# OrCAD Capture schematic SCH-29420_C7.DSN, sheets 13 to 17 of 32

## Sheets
13 P11_MX8QM_GND: size A2
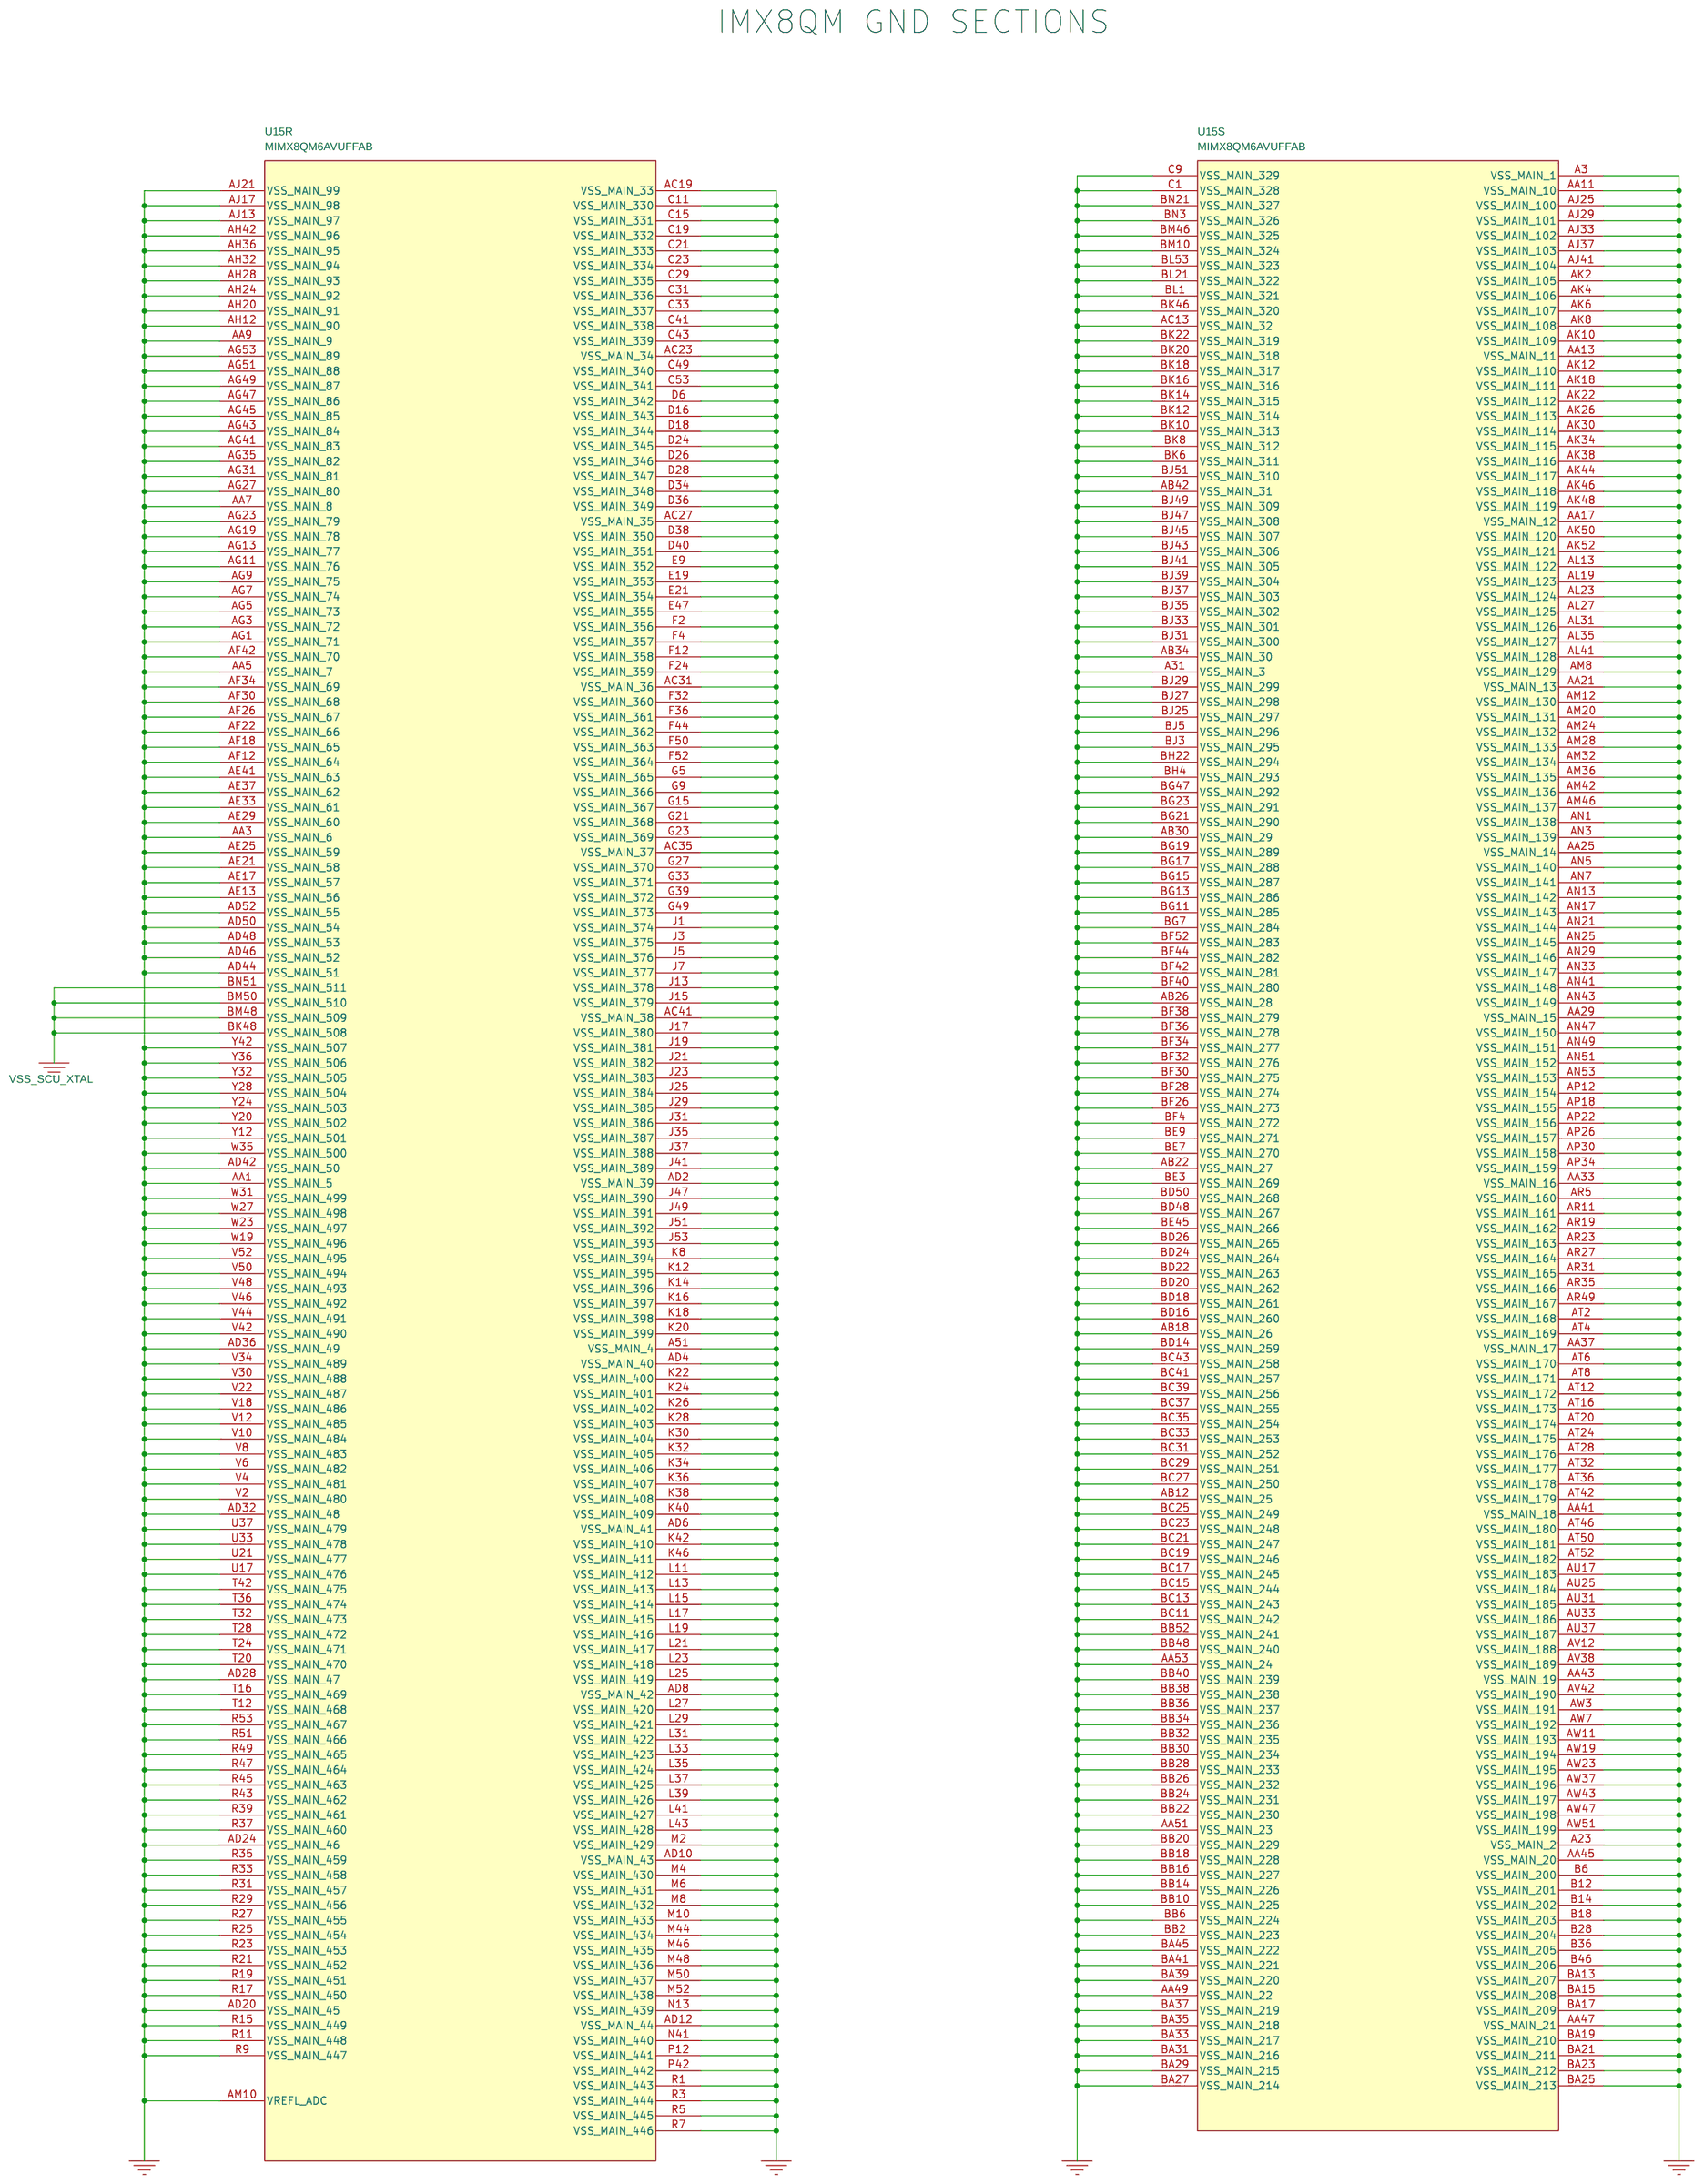
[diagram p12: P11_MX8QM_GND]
14 P12_MX8QM_SECTIONS_1: size A1
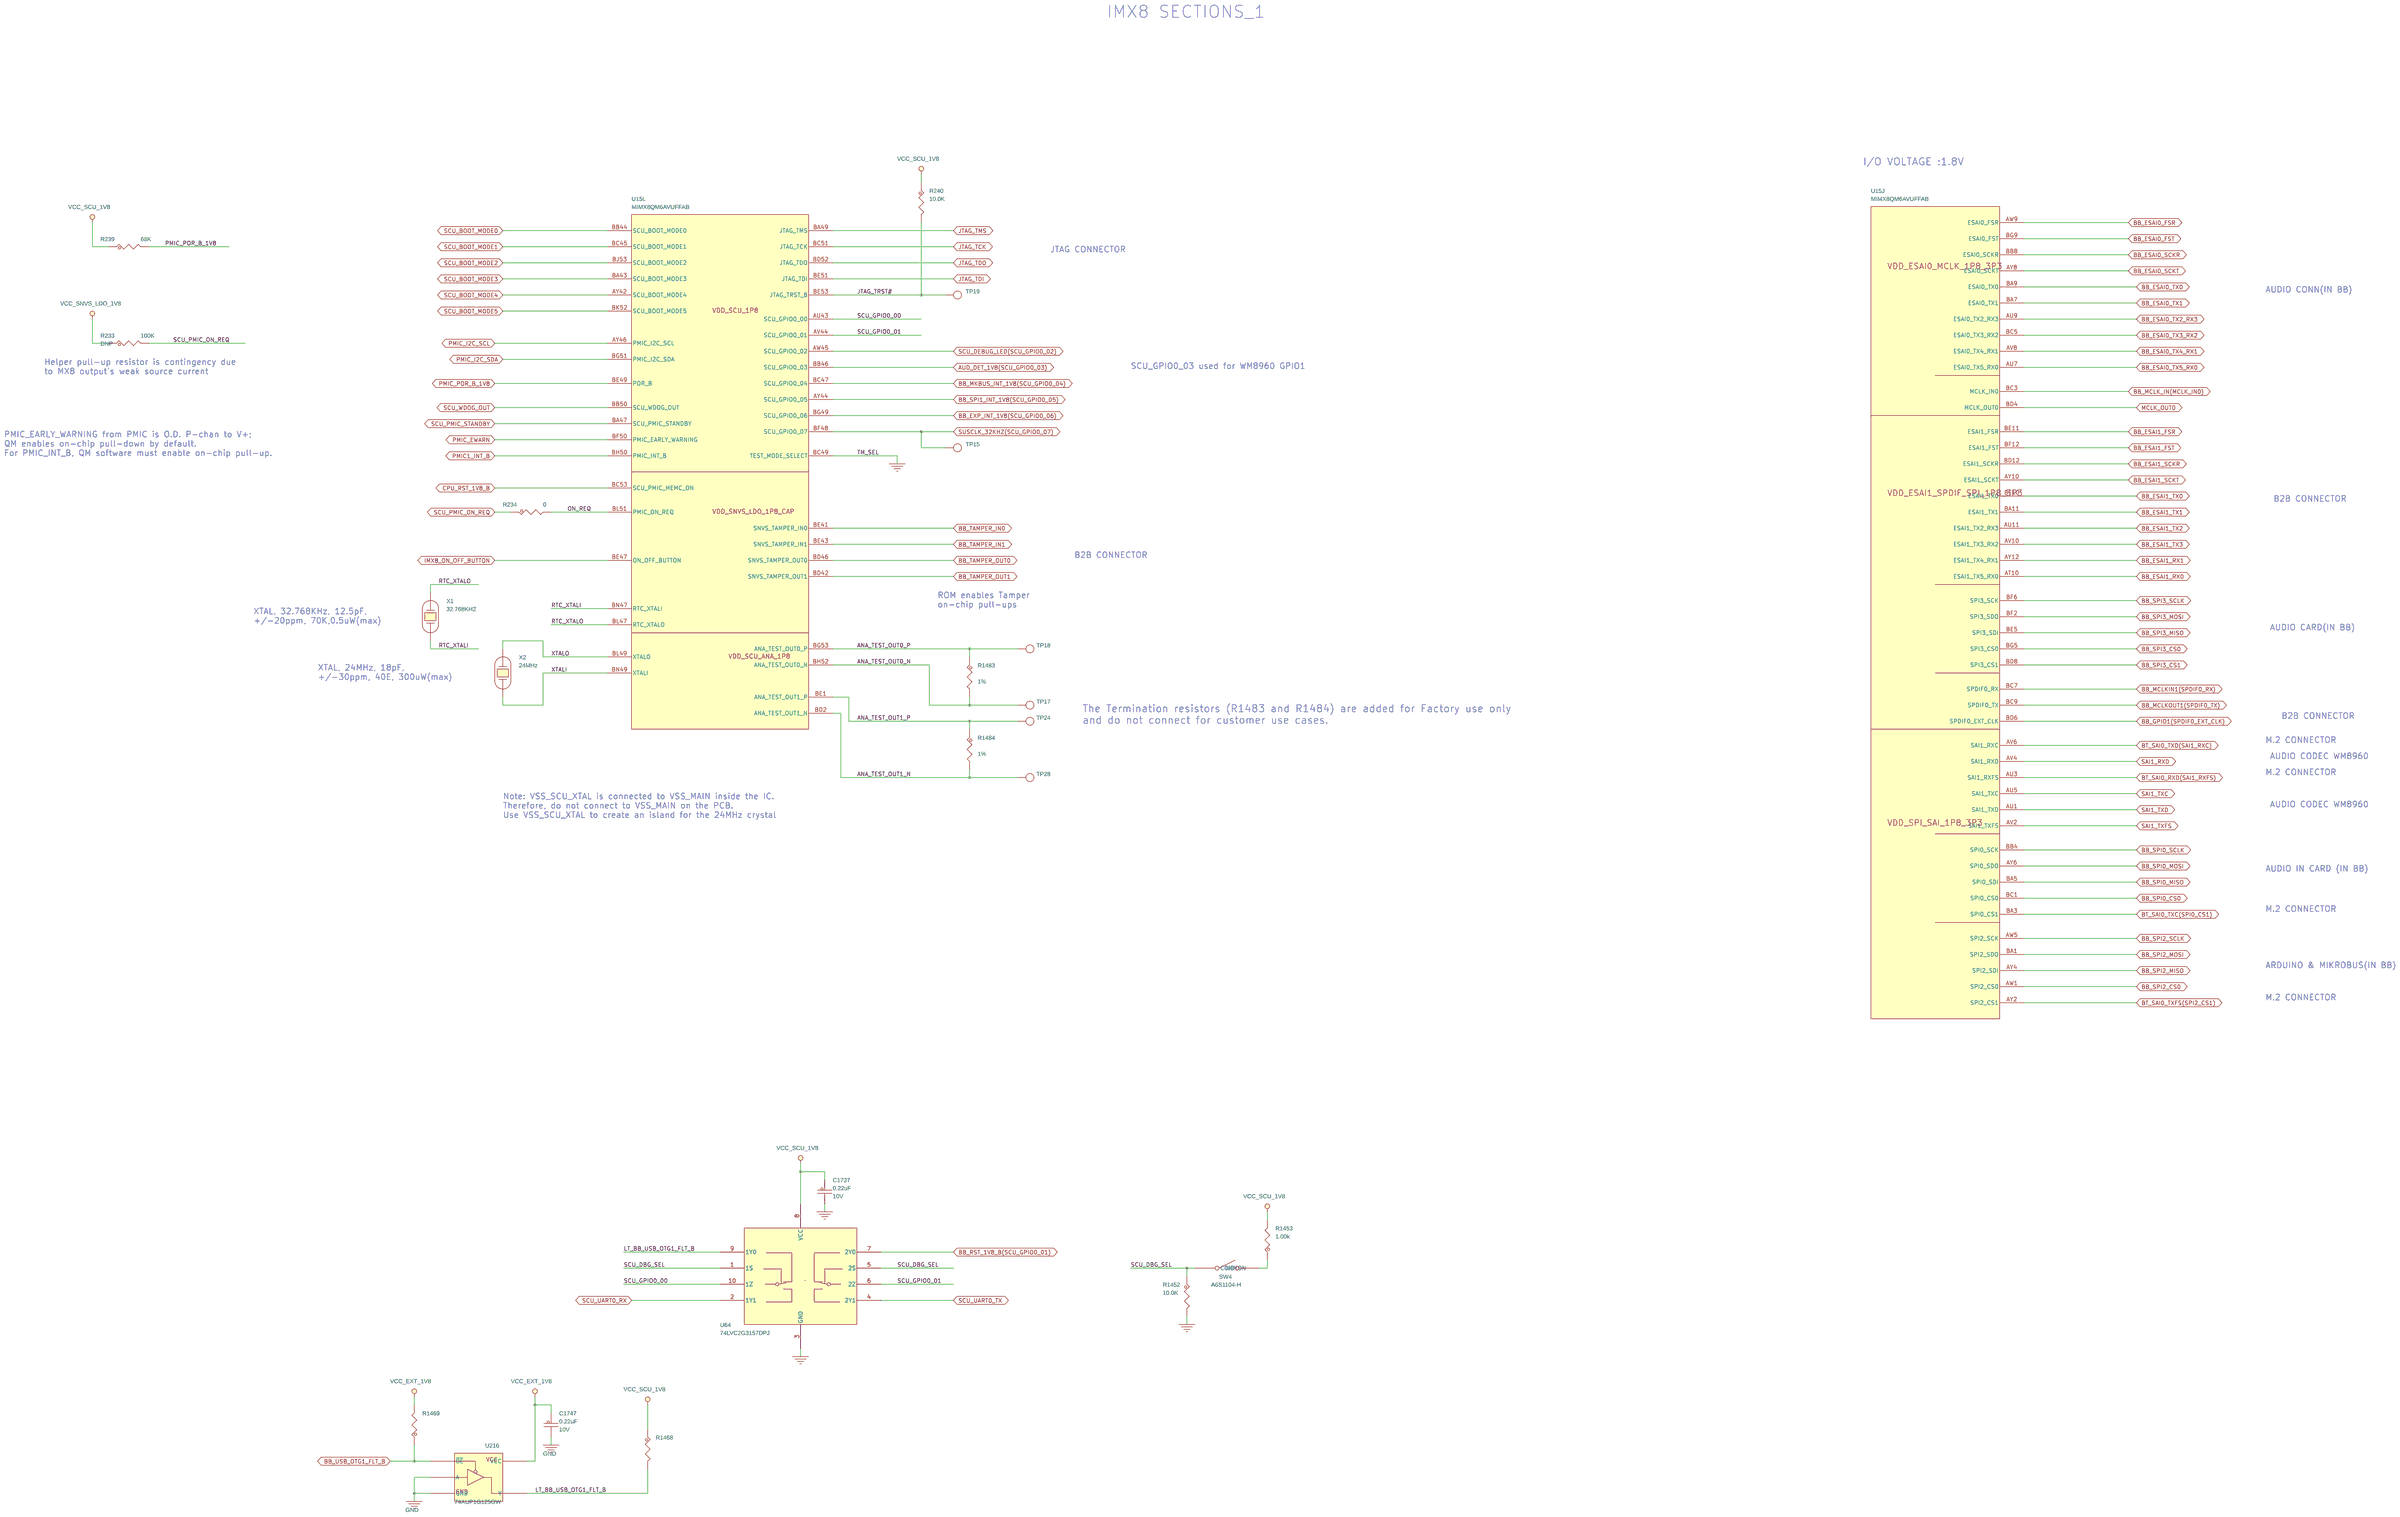
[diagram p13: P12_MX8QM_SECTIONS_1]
15 P13_MX8QM_SECTIONS_2: size A2
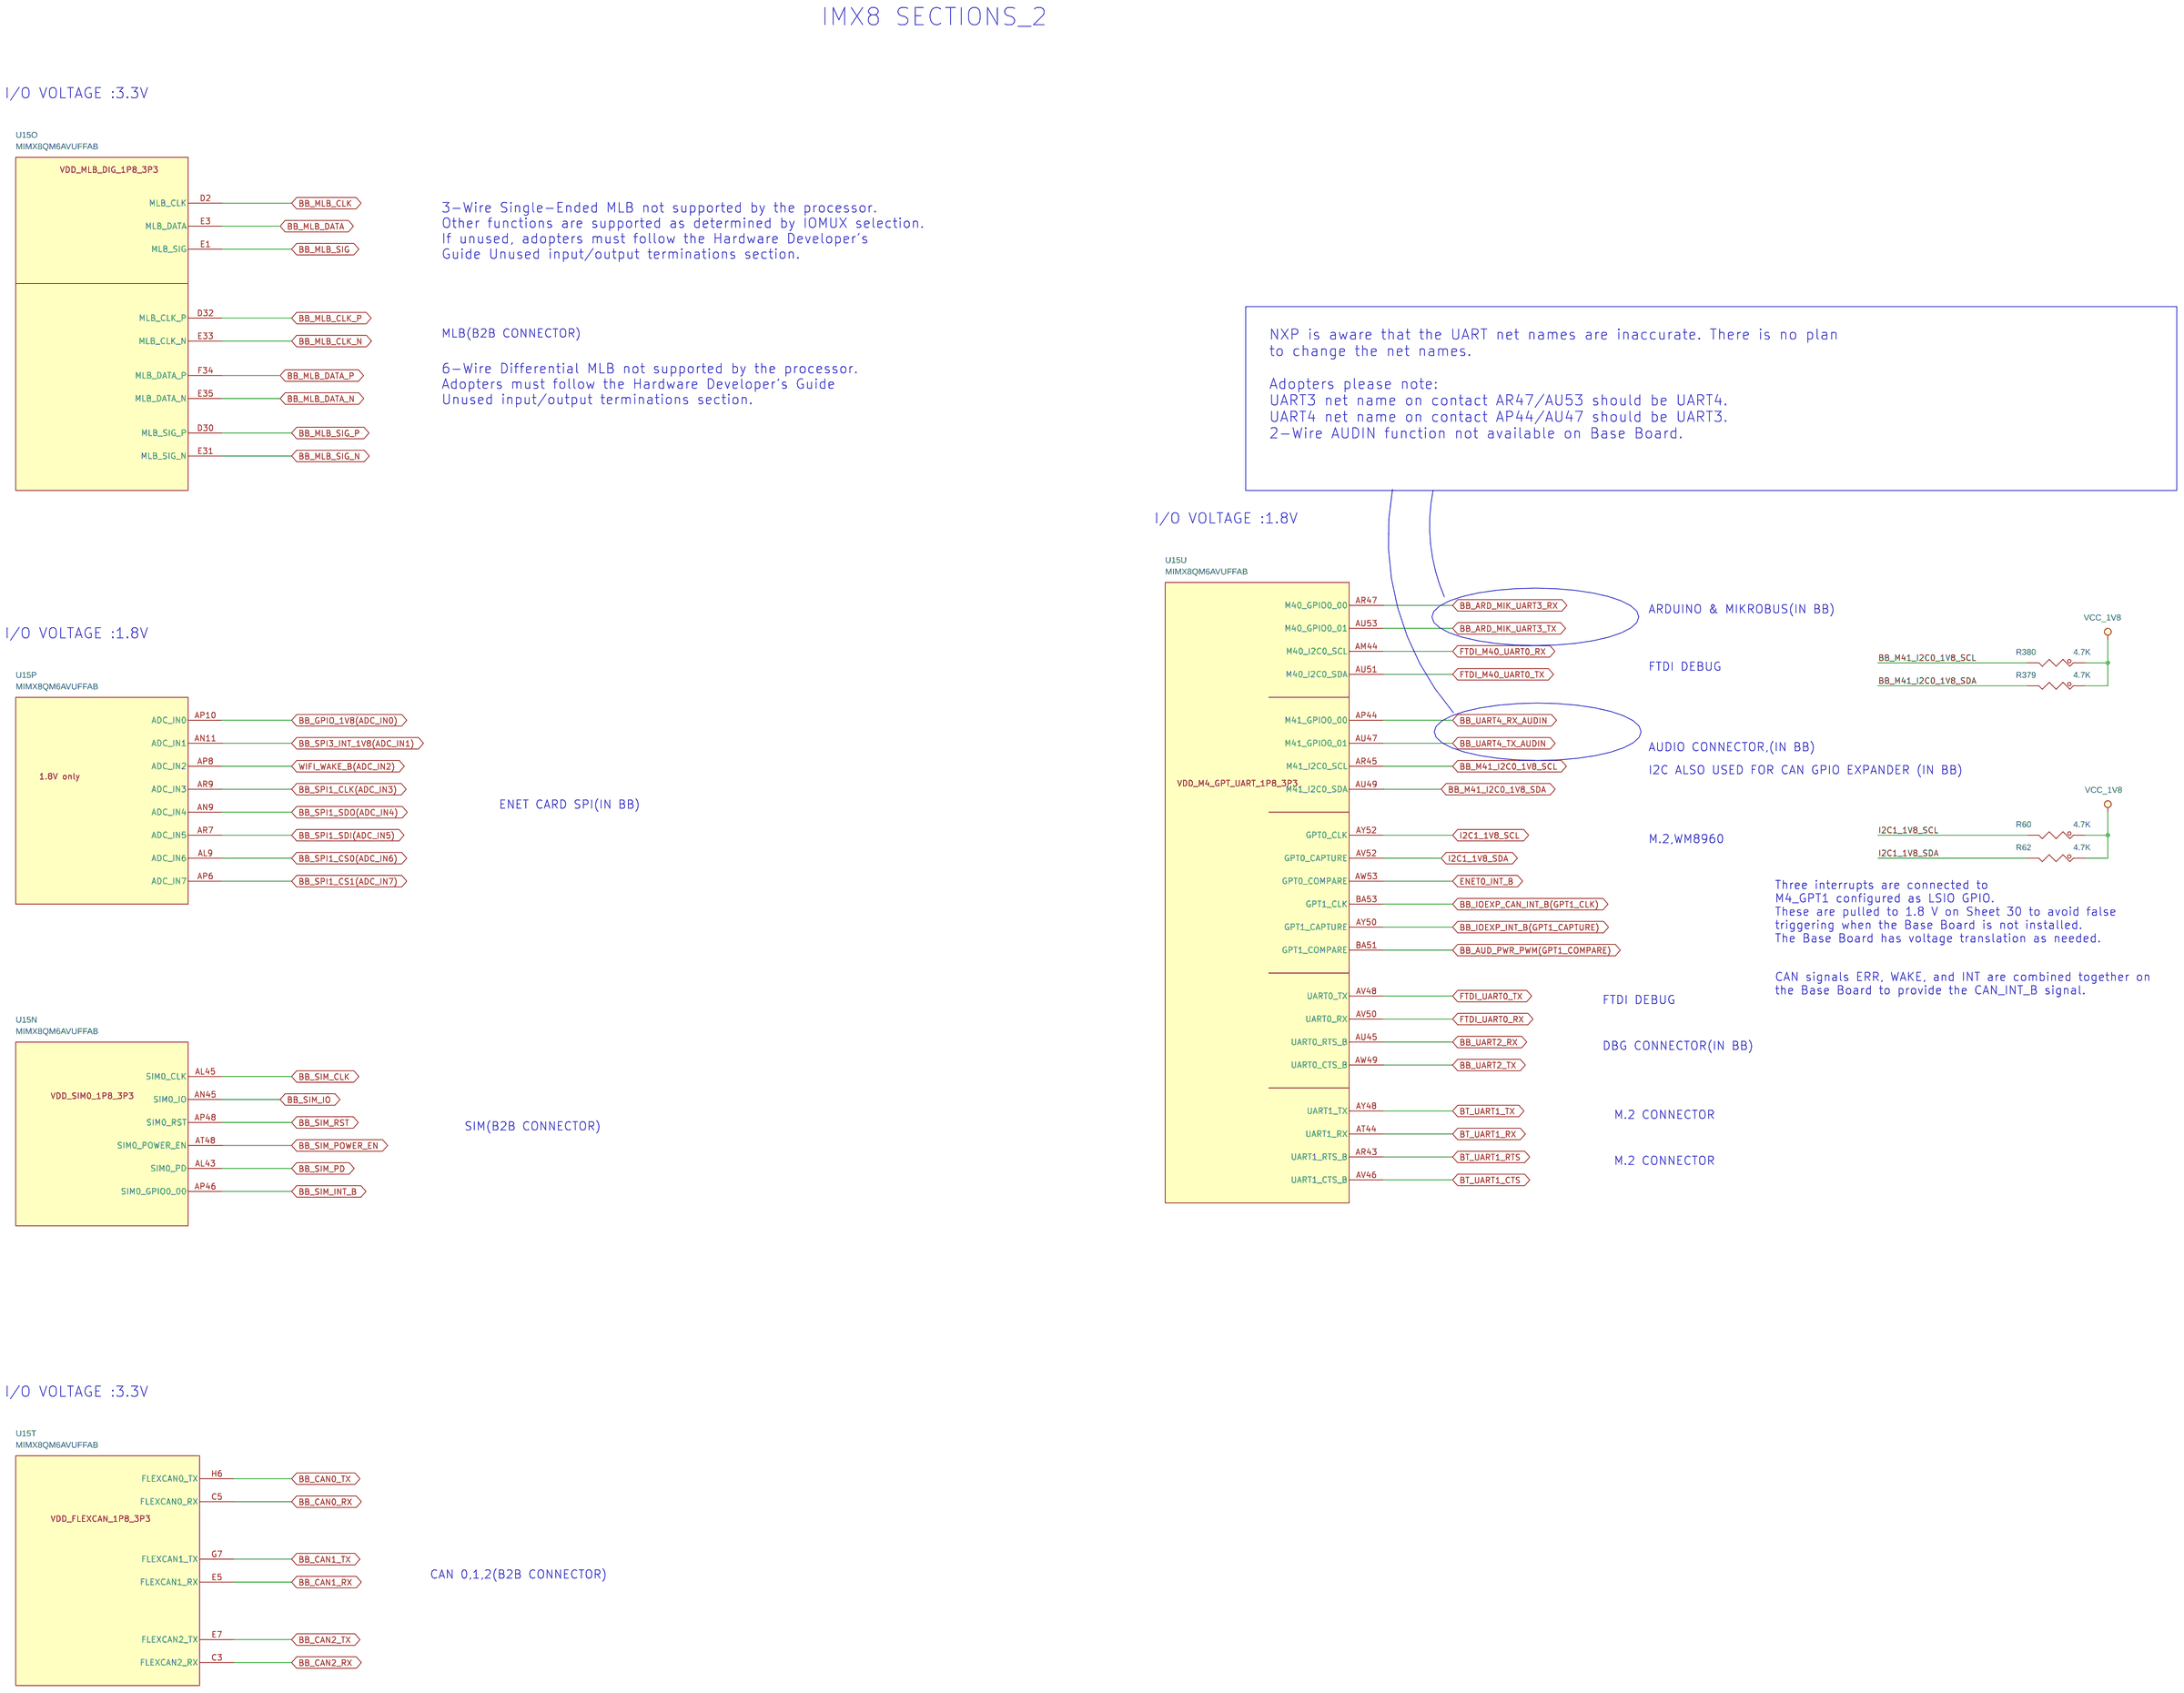
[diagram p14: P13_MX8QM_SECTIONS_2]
16 P14_LPDDR4_DRAM_1: size A2
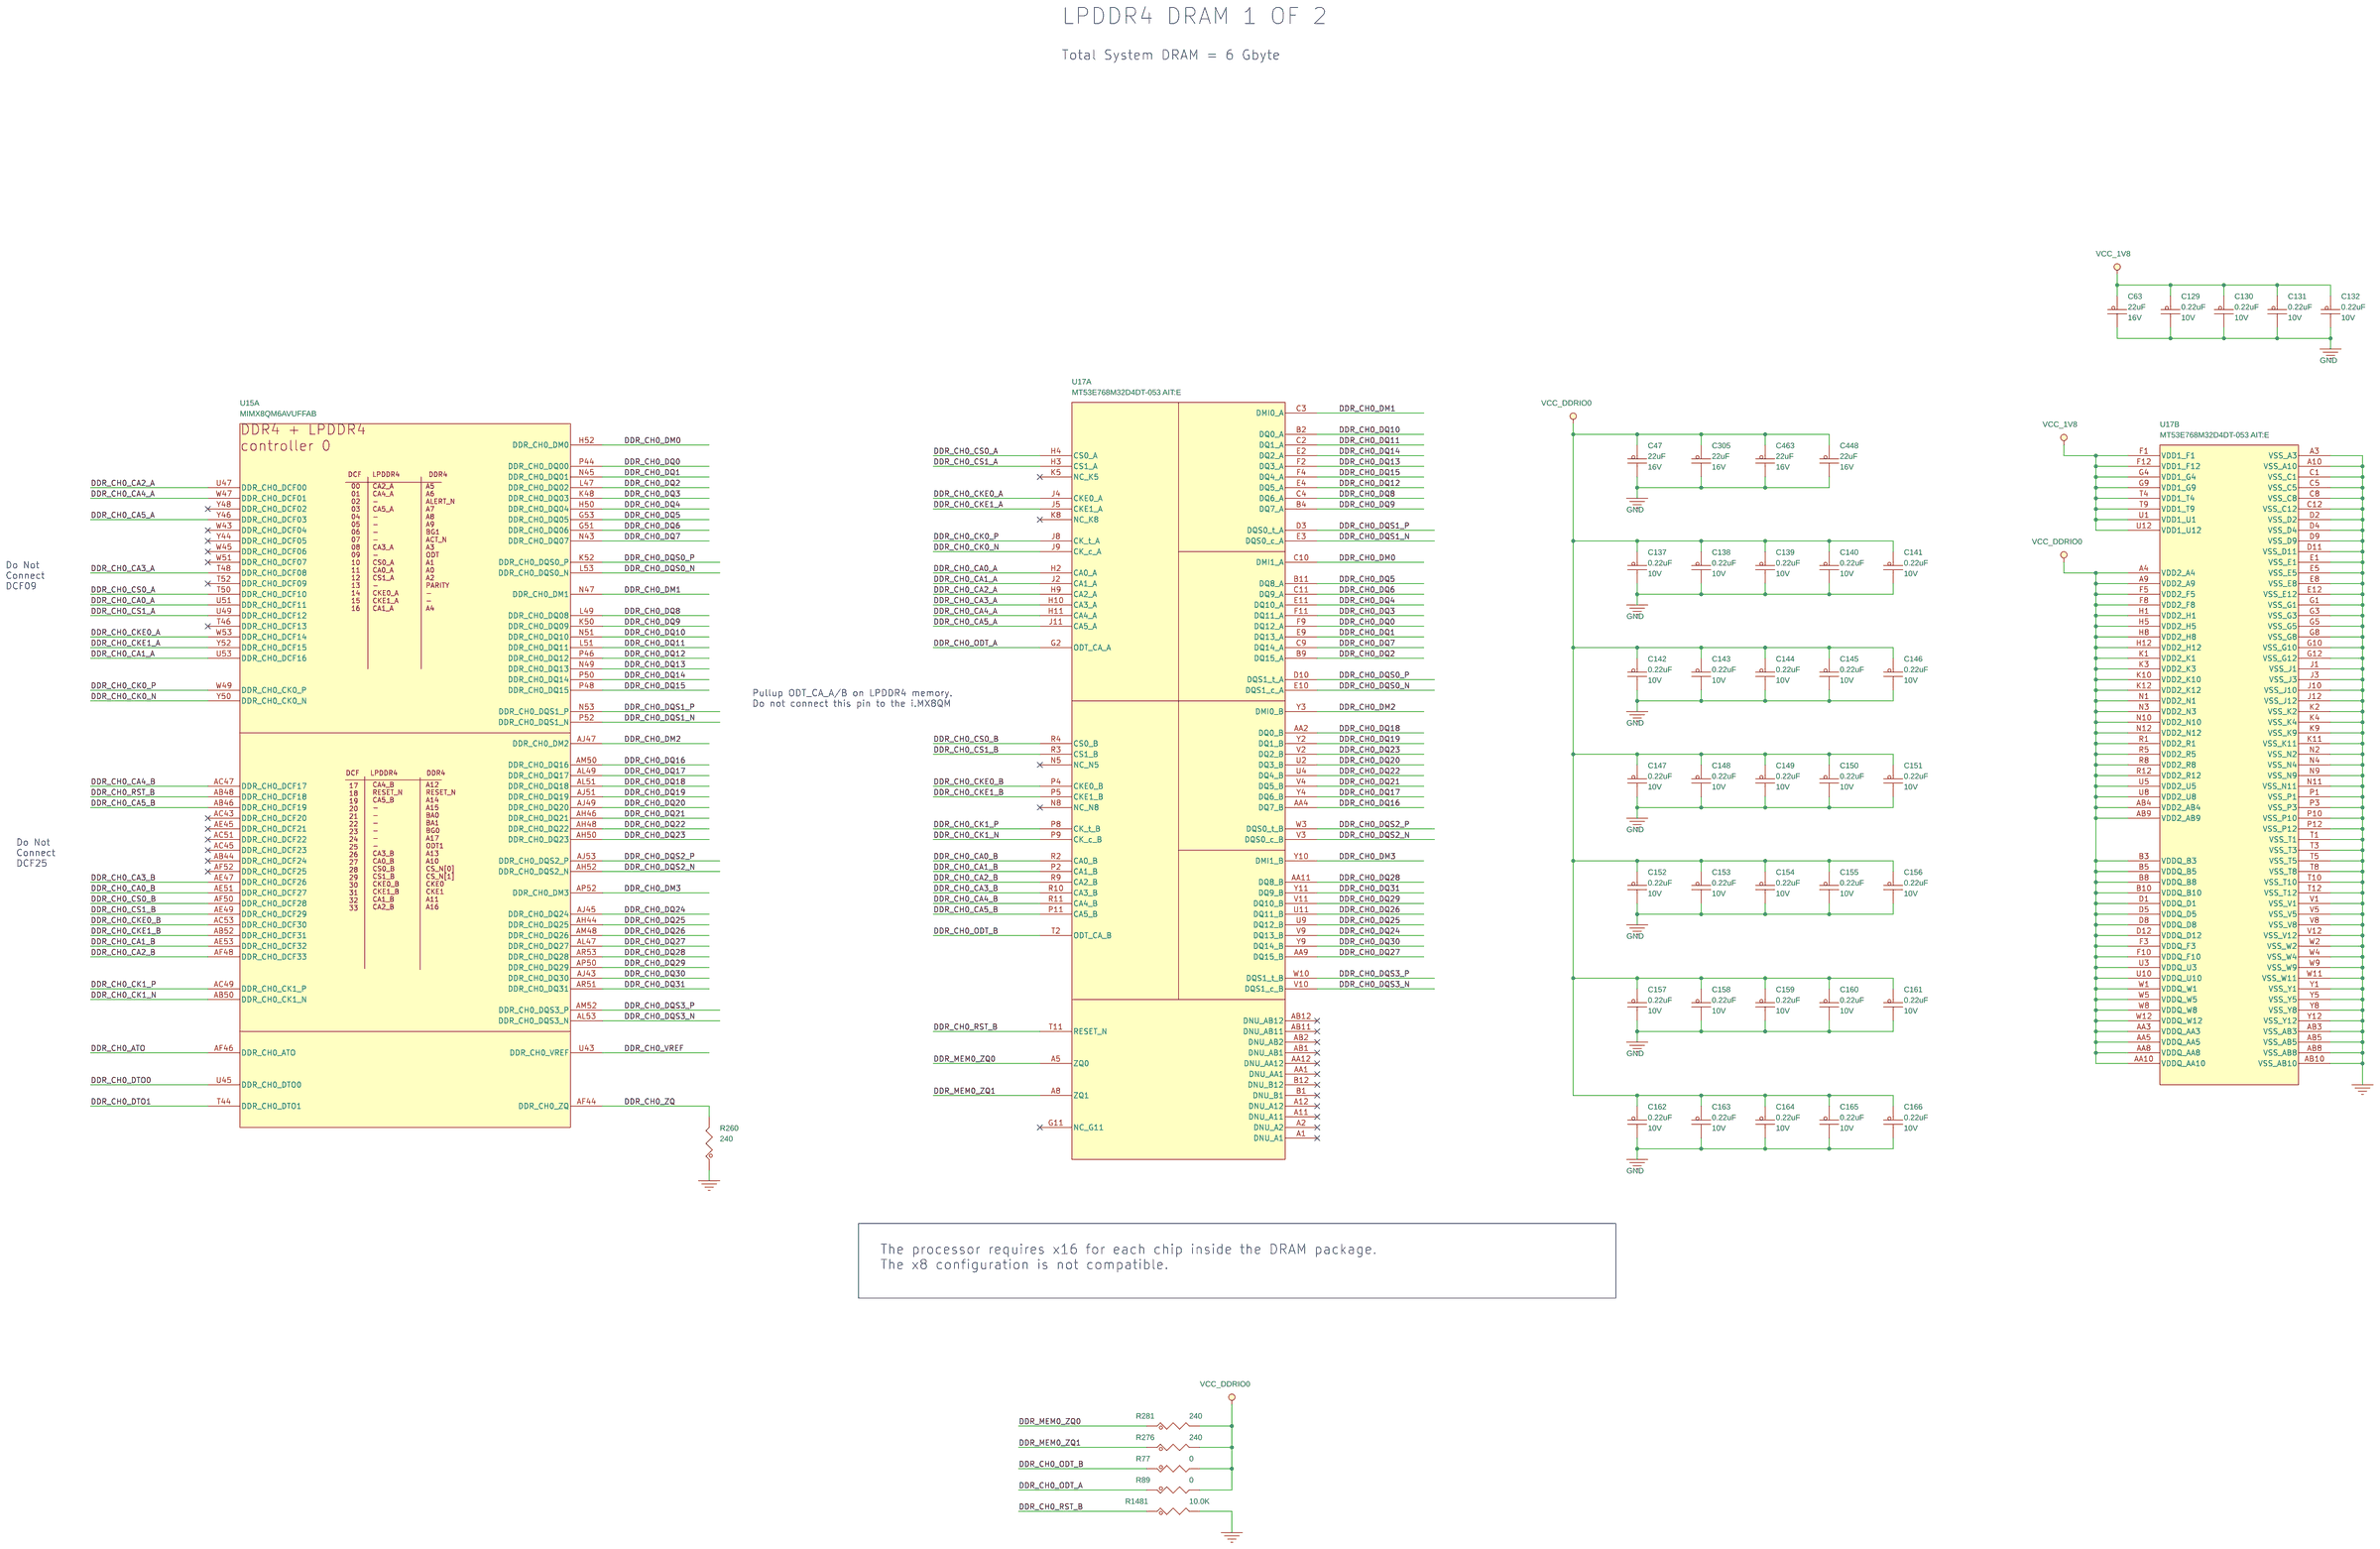
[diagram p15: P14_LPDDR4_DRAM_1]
17 P15_LPDDR4_DRAM_2: size A2
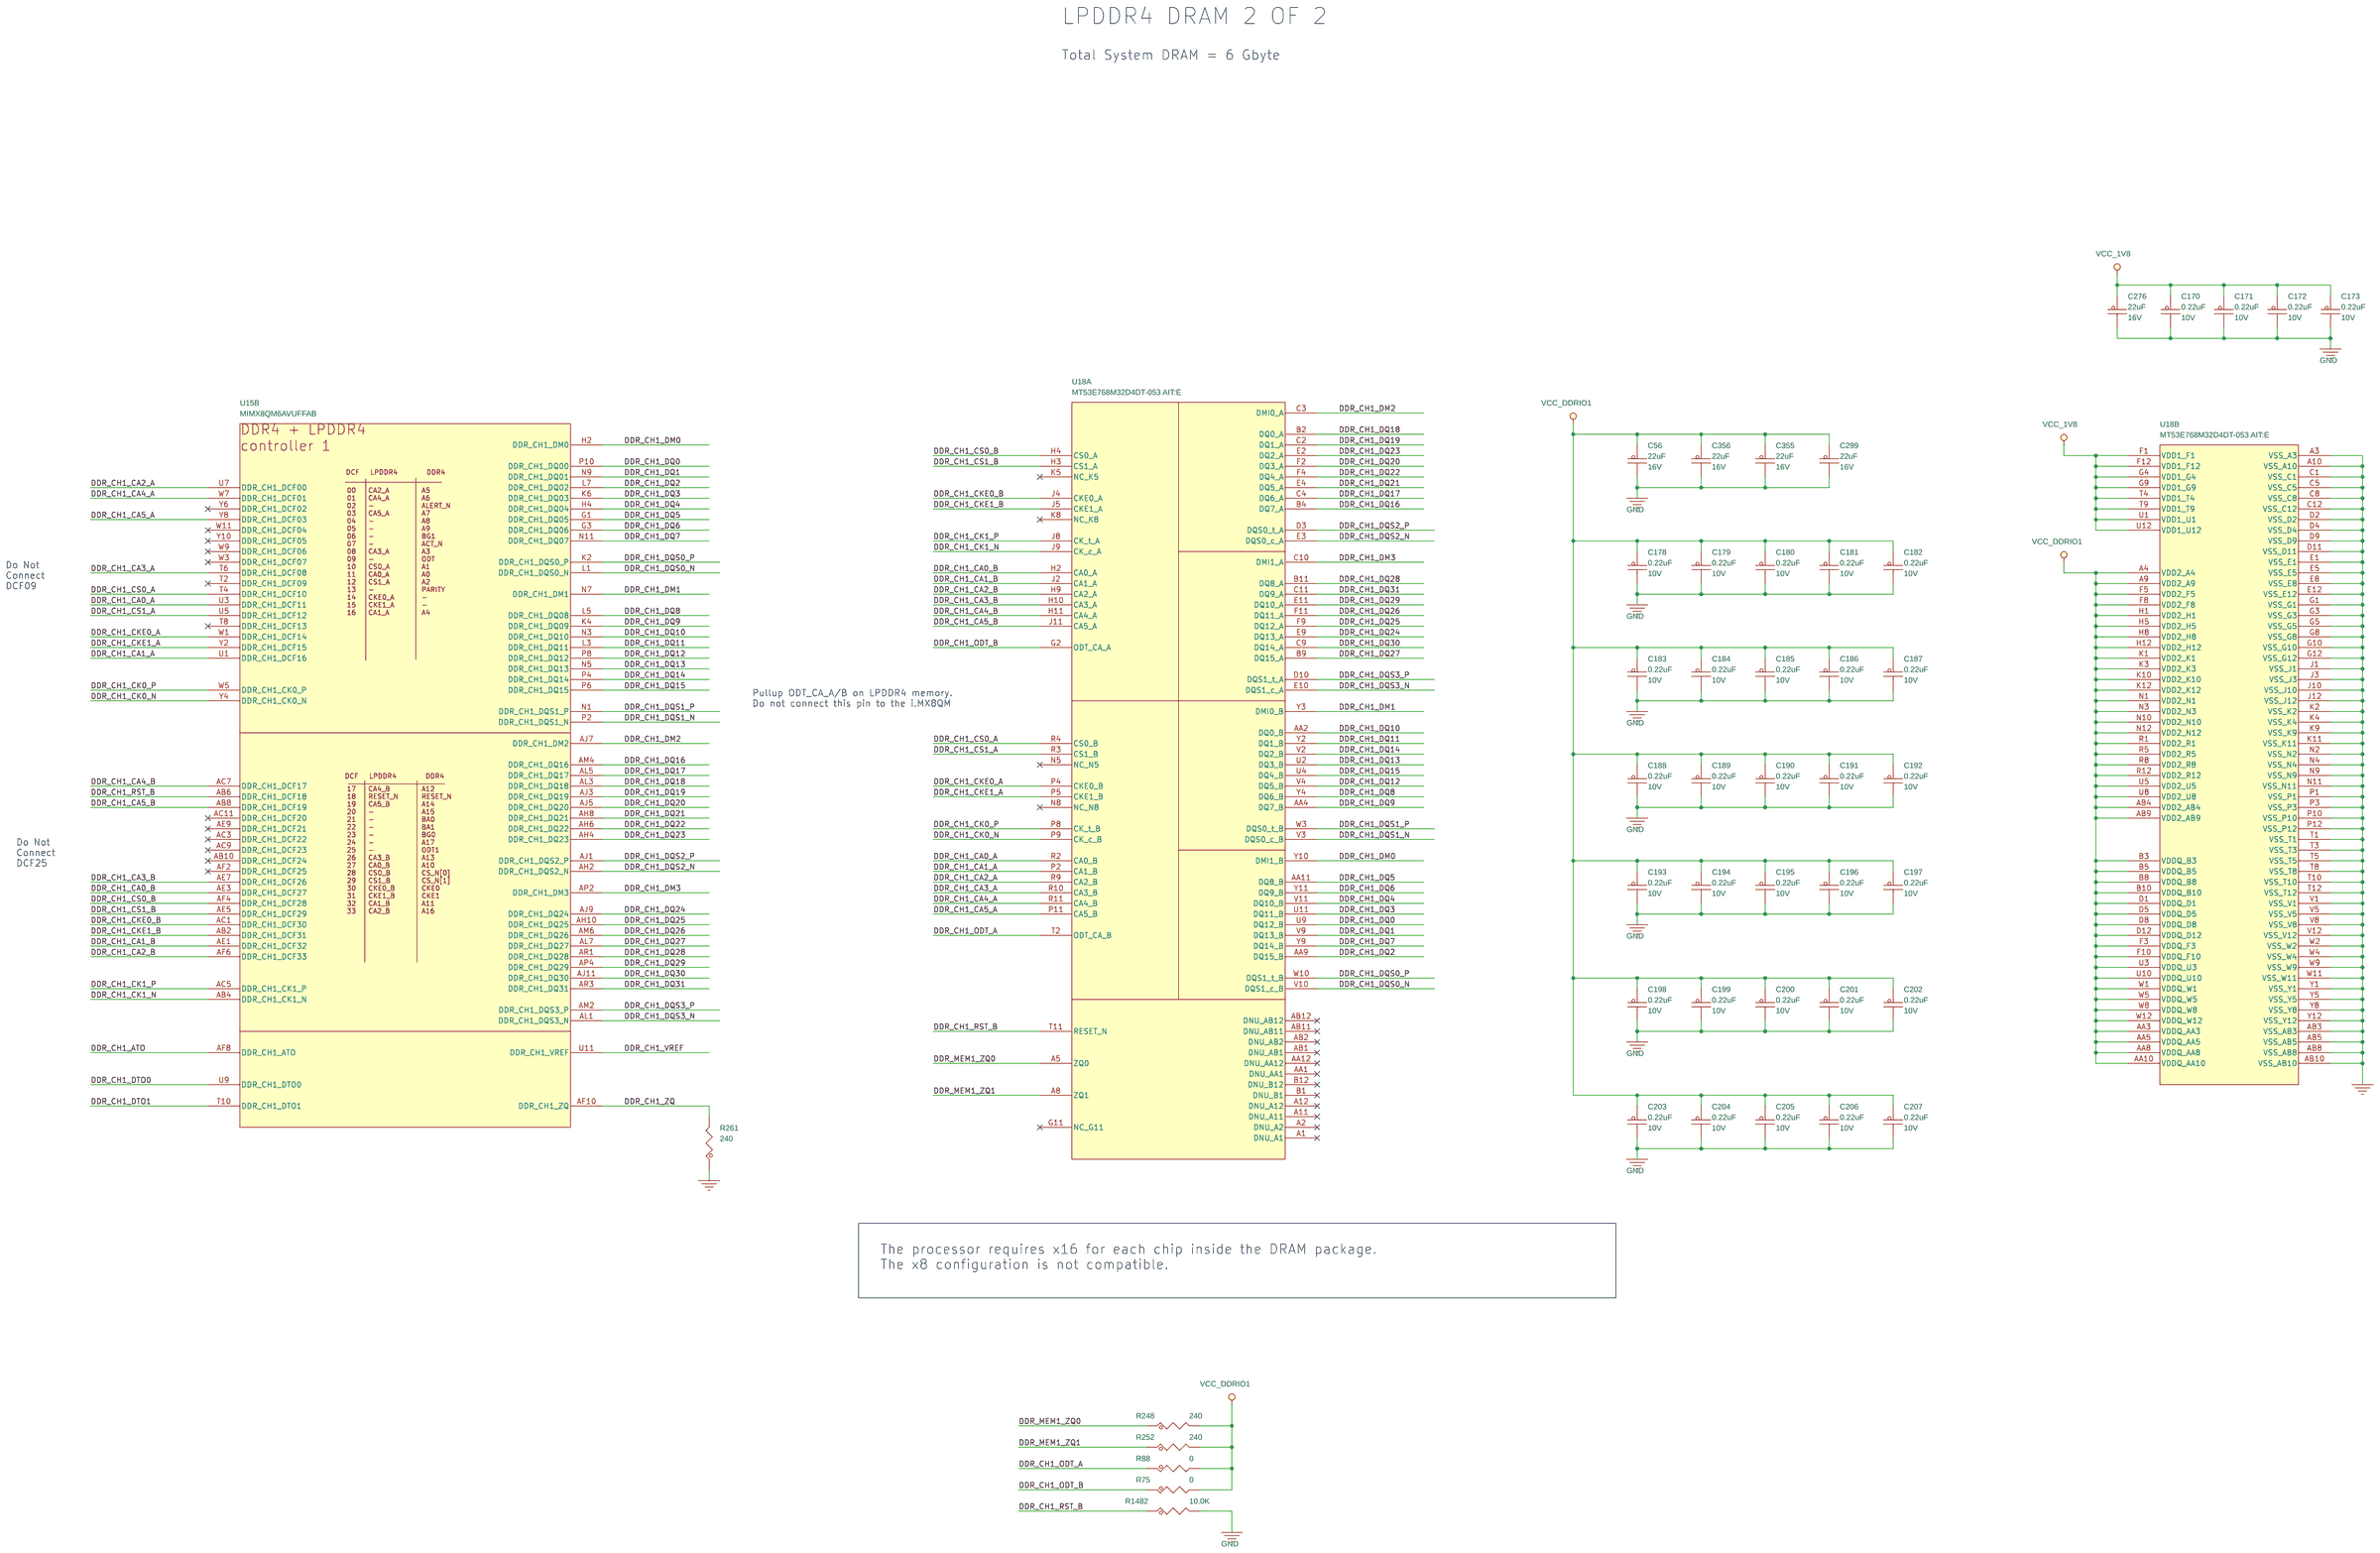
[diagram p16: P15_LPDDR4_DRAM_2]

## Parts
sheet P12_MX8QM_SECTIONS_1
C1737  0.22uF  [CC0402_25]
C1747  0.22uF  [0402_CC]
R233  100K  [RC0402_25]
R234  0  [RC0402_25]
R239  68K  [RC0402_25]
R240  10.0K  [RC0402_25]
R1452  10.0K  [RC0402_25]
R1453  1.00k  [RC0402_25]
R1468  10K  [RC0402_25]
R1469  68K  [RC0402_25]
R1483  100  [RC0402_25]
R1484  100  [RC0402_25]
SW4  A6S1104-H  [sw2_6p4x3p68_sm]
TP15  TPAD_050  [TPAD_050]
TP17  TPAD_020  [tpad_020]
TP18  TPAD_020  [tpad_020]
TP19  TPAD_050  [TPAD_050]
TP24  TPAD_020  [tpad_020]
TP28  TPAD_020  [tpad_020]
U64  74LVC2G3157DPJ  [TSSOP10_0P5_3X3MM]
U216  74AUP1G125GW  [SC70-5]
X1  32.768KHZ  [XTAL2-3P2X1P5-SM]
X2  24MHz  [xtal2_4_5p2x3p4]
sheet P13_MX8QM_SECTIONS_2
R60  4.7K  [RC0402_25]
R62  4.7K  [RC0402_25]
R379  4.7K  [RC0402_25]
R380  4.7K  [RC0402_25]
sheet P14_LPDDR4_DRAM_1
C47  22uF  [CC1210]
C63  22uF  [CC1210]
C129  0.22uF  [CC0402_25]
C130  0.22uF  [CC0402_25]
C131  0.22uF  [CC0402_25]
C132  0.22uF  [CC0402_25]
C137  0.22uF  [CC0402_25]
C138  0.22uF  [CC0402_25]
C139  0.22uF  [CC0402_25]
C140  0.22uF  [CC0402_25]
C141  0.22uF  [CC0402_25]
C142  0.22uF  [CC0402_25]
C143  0.22uF  [CC0402_25]
C144  0.22uF  [CC0402_25]
C145  0.22uF  [CC0402_25]
C146  0.22uF  [CC0402_25]
C147  0.22uF  [CC0402_25]
C148  0.22uF  [CC0402_25]
C149  0.22uF  [CC0402_25]
C150  0.22uF  [CC0402_25]
C151  0.22uF  [CC0402_25]
C152  0.22uF  [CC0402_25]
C153  0.22uF  [CC0402_25]
C154  0.22uF  [CC0402_25]
C155  0.22uF  [CC0402_25]
C156  0.22uF  [CC0402_25]
C157  0.22uF  [CC0402_25]
C158  0.22uF  [CC0402_25]
C159  0.22uF  [CC0402_25]
C160  0.22uF  [CC0402_25]
C161  0.22uF  [CC0402_25]
C162  0.22uF  [CC0402_25]
C163  0.22uF  [CC0402_25]
C164  0.22uF  [CC0402_25]
C165  0.22uF  [CC0402_25]
C166  0.22uF  [CC0402_25]
C305  22uF  [CC1210]
C448  22uF  [CC1210]
C463  22uF  [CC1210]
R77  0  [RC0402_25]
R89  0  [RC0402_25]
R260  240  [RC0402_25]
R276  240  [RC0402_25]
R281  240  [RC0402_25]
R1481  10.0K  [RC0402_25]
U17  MT53E768M32D4DT-053 AIT:E  [bga200_0p65x0p8_10p1x14p6]  (sections A,B)
sheet P15_LPDDR4_DRAM_2
C56  22uF  [CC1210]
C170  0.22uF  [CC0402_25]
C171  0.22uF  [CC0402_25]
C172  0.22uF  [CC0402_25]
C173  0.22uF  [CC0402_25]
C178  0.22uF  [CC0402_25]
C179  0.22uF  [CC0402_25]
C180  0.22uF  [CC0402_25]
C181  0.22uF  [CC0402_25]
C182  0.22uF  [CC0402_25]
C183  0.22uF  [CC0402_25]
C184  0.22uF  [CC0402_25]
C185  0.22uF  [CC0402_25]
C186  0.22uF  [CC0402_25]
C187  0.22uF  [CC0402_25]
C188  0.22uF  [CC0402_25]
C189  0.22uF  [CC0402_25]
C190  0.22uF  [CC0402_25]
C191  0.22uF  [CC0402_25]
C192  0.22uF  [CC0402_25]
C193  0.22uF  [CC0402_25]
C194  0.22uF  [CC0402_25]
C195  0.22uF  [CC0402_25]
C196  0.22uF  [CC0402_25]
C197  0.22uF  [CC0402_25]
C198  0.22uF  [CC0402_25]
C199  0.22uF  [CC0402_25]
C200  0.22uF  [CC0402_25]
C201  0.22uF  [CC0402_25]
C202  0.22uF  [CC0402_25]
C203  0.22uF  [CC0402_25]
C204  0.22uF  [CC0402_25]
C205  0.22uF  [CC0402_25]
C206  0.22uF  [CC0402_25]
C207  0.22uF  [CC0402_25]
C276  22uF  [CC1210]
C299  22uF  [CC1210]
C355  22uF  [CC1210]
C356  22uF  [CC1210]
R75  0  [RC0402_25]
R88  0  [RC0402_25]
R248  240  [RC0402_25]
R252  240  [RC0402_25]
R261  240  [RC0402_25]
R1482  10.0K  [RC0402_25]
U18  MT53E768M32D4DT-053 AIT:E  [bga200_0p65x0p8_10p1x14p6]  (sections A,B)
sheet P20_USB3.x_TYPE_C
U15  MIMX8QM6AVUFFAB  [imx8_bga_1313]  (sections A,B,C,D,E,F,G,H,I,J,K,L,M,N,O,P,Q,R,S,T,U)

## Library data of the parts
C129-C132 C137-C166 C170-C173 C178-C207 C1737 C1747 = CAP_NP: CAP CER 0.22uF 10V 10% X7R AEC-Q200 0402; AGILE_PN: 150-79031; CAD_APPROVED: Yes; EN: 102-1-01816; FPLIST: CC0402_25,CC0402_HD,0402_CC; HEIGHT: 0.55MM; MFG_NAME01: TDK; MFG_PN01: CGA2B1X7R1A224K050BC; ROHS: Yes; TOL: 10%; Tolerance: 10%; VOLTAGE: 10V
R233 = RES: RES MF 100K 1/16W 5% 0402; AGILE_PN: 470-75597; ASSY_OPT: DNP; CAD_APPROVED: Yes; EN: 101-1-02817; FPLIST: RC0402_25,RC0402_HD,0402_CC; HEIGHT: 0.40 MM; MFG_NAME01: VENKEL COMPANY; MFG_PN01: CR0402-16W-104JT; ROHS: Yes; TOL: 5%; Tolerance: 5%
R75 R77 R88 R89 R234 = RES: RES MF ZERO OHM 1/16W -- AEC-Q200 0402; AGILE_PN: 470-80742; CAD_APPROVED: Yes; EN: 101-1-00001; FPLIST: RC0402_25,RC0402_HD,0402_CC; HEIGHT: 0.45 MM; MFG_NAME01: VISHAY INTERTECHNOLOGY; MFG_PN01: CRCW04020000Z0ED; ROHS: Yes
R239 = RES: RES MF 68K 1/16W 5% 0402; AGILE_PN: 470-30330; CAD_APPROVED: Yes; EN: 101-1-02813; FPLIST: RC0402_25,RC0402_HD,0402_CC; HEIGHT: 0.4MM; MFG_NAME01: TYCO ELECTRONICS; MFG_PN01: CRG0402J68K; ROHS: Yes; TOL: 5%; Tolerance: 5%
R240 R1452 R1481 R1482 = RES: RES MF 10.0K 1/16W 1% 0402; AGILE_PN: 470-80574; CAD_APPROVED: Yes; EN: 101-1-00389; FPLIST: RC0402_25,RC0402_HD,0402_CC; HEIGHT: 0.4MM; MFG_NAME01: WALSIN TECHNOLOGY CORP.; MFG_PN01: WR04X1002FTL; ROHS: Yes; TOL: 1%; Tolerance: 1%
R1453 = RES: RES MF 1.00k Ohm 1/16W 1% AEC-Q200 0402; AGILE_PN: 470-80511; CAD_APPROVED: Yes; EN: 101-1-00293; FPLIST: RC0402_25,RC0402_HD,0402_CC; HEIGHT: 0.4 MM; MFG_NAME01: KOA SPEER; MFG_PN01: RK73H1ETTP1001F; ROHS: Yes; TOL: 1%; Tolerance: 1%
R1468 = RES: RES MF 10K 1/16W 5% 0402; AGILE_PN: 470-75557; CAD_APPROVED: Yes; EN: 101-1-02793; FPLIST: RC0402_25,RC0402_HD,0402_CC; HEIGHT: 0.4 MM; MFG_NAME01: VISHAY INTERTECHNOLOGY; MFG_PN01: CRCW040210K0JNED; ROHS: Yes; TOL: 5%; Tolerance: 5%
R1469 = RES: RES MF 68K  1/16W 1% AEC-Q200 0402; AGILE_PN: 470-31042; CAD_APPROVED: Yes; EN: 101-1-03542; FPLIST: RC0402_25,RC0402_HD,0402_CC; HEIGHT: 0.40 MM; MFG_NAME01: VISHAY INTERTECHNOLOGY; MFG_PN01: CRCW040268K0FKED; PRIORITY_PN: 006-00730; ROHS: Yes; ROOM: JTAG; SIGNAL_MODEL: DEFAULT_RESISTOR_68000OHM_2_1; TOL: 1%; Tolerance: 1%
R1483 R1484 = RES: RES MF 100 OHM 1/16W 1% 0402; AGILE_PN: 470-30454; CAD_APPROVED: Yes; EN: 101-1-00197; FPLIST: RC0402_25,RC0402_HD,0402_CC; HEIGHT: 0.4 MM; MFG_NAME01: THYE MING TECH CO LTD; MFG_PN01: CR-02FL6--100R; ROHS: Yes; SIGNAL_MODEL: DEFAULT_RESISTOR_100OHM_2_1; TOL: 1%; Tolerance: 1%
SW4 = SW2P: SW SPST DIP SLD 25mA 24V SMD; AGILE_PN: 510-78107; CAD_APPROVED: Yes; EN: 205-1-00234; HEIGHT: 4.5MM; MFG_NAME01: OMRON; MFG_PN01: A6S-1104-H; ROHS: Yes
TP15 TP19 = TESTLOOP: TEST POINT PAD 50MIL DIA SMT, NO PART TO ORDER; AGILE_PN: 211-76644; CAD_APPROVED: Yes; HEIGHT: 0.1MM; MFG_NAME01: NOTACOMPONENT; MFG_PN01: NOTACOMPONENT; ROHS: Yes
TP17 TP18 TP24 TP28 = TESTLOOP: TEST POINT PAD 0.5MM DIA SMT, NO PART TO ORDER; AGILE_PN: 211-77484; CAD_APPROVED: Yes; HEIGHT: 0.1MM; ROHS: Yes
U64 = 74LVC2G3157DPJ: IC LIN SW DUAL SPDT 1.65-5.5V TSSOP10; AGILE_PN: 315-81080; CAD_APPROVED: Yes; EN: 301-0-01547; HEIGHT: 1.1 MM; MFG_NAME01: NEXPERIA; MFG_PN01: 74LVC2G3157DP,118; ROHS: Yes
U216 = 1G125: IC BUFFER/LINE DRIVER 3STATE 0.8-3.6V SC70-5; AGILE_PN: 315-80956; CAD_APPROVED: Yes; EN: 301-0-01520; HEIGHT: 1.1MM; MFG_NAME01: NEXPERIA; MFG_PN01: 74AUP1G125GW,125; ROHS: Yes
X1 = XTAL: XTAL 32.768KHZ 12.5PF 20PPM 3.2X1.5MM SMT; AGILE_PN: 230-77653; CAD_APPROVED: Yes; EN: 108-1-00009; HEIGHT: 0.9MM; MFG_NAME01: Abracon Corporation; MFG_PN01: ABS07-32.768KHZ-T; ROHS: Yes
X2 = XTAL: XTAL 24MHz 18PF 5x3.2mm SMT; AGILE_PN: 230-78202; CAD_APPROVED: Yes; EN: 108-1-00039; HEIGHT: 1.35MM; MFG_NAME01: CTS; MFG_PN01: 445I23D24M00000; ROHS: Yes; Temp_Range: -40C to +85C
R60 R62 R379 R380 = RES: RES MF 4.7K 1/16W 5% 0402; AGILE_PN: 470-75626; CAD_APPROVED: Yes; EN: 101-1-02785; FPLIST: RC0402_25,RC0402_HD,0402_CC,RC0402_X2; HEIGHT: 0.41mm; MFG_NAME01: NIC COMPONENTS CORP; MFG_PN01: NRCL04J472TRF; ROHS: Yes; TOL: 5%; Tolerance: 5%
C47 C56 C63 C276 C299 C305 C355 C356 C448 C463 = CAP_NP: CAP CER 22uF 16V 20% X7R AEC-Q200 HF 1210; AGILE_PN: 150-79354; CAD_APPROVED: Yes; EN: 102-1-02278; FPLIST: CC1210,1210_CC; HEIGHT: 2.7MM; MFG_NAME01: Taiyo Yuden; MFG_PN01: EMK325B7226MMHT; ROHS: Yes; TOL: 20%; Tolerance: 20%; VOLTAGE: 16V
R248 R252 R260 R261 R276 R281 = RES: RES MF 240 OHM 1/16W 1% 0402; AGILE_PN: 470-30776; CAD_APPROVED: Yes; EN: 101-1-03473; FPLIST: RC0402_25,RC0402_HD,0402_CC; HEIGHT: 0.40 MM; MFG_NAME01: WALSIN TECHNOLOGY CORP.; MFG_PN01: WR04X2400FTL; ROHS: Yes; TOL: 1%; Tolerance: 1%
U17 U18 = MT53B768M32D4NQ_200P: IC MEM MOBILE LPDDR4 SDRAM 768 Meg x 32 1.1V VFBGA200; AGILE_PN: 334-77856; CAD_APPROVED: Yes; HEIGHT: 0.95MM; MFG_NAME01: MICRON; ROHS: Yes; Temp Range: -40C to +95C; VOLTAGE: 1.1V
U15 = PIMX8QM6AVUFFAB_BGA1313: IC CPU QUADMAX 2xA72 1.6GHz 4xA53 1.2GHZ M4 264MHZ FCPBGA1313; AGILE_PN: 330-77094; CAD_APPROVED: Yes; HEIGHT: 2.52MM; MFG_NAME01: NXP SEMICONDUCTORS; ROHS: Yes; Temp Range: -40°C to 125°C

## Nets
GND: C47.2 C56.2 C63.2 C129.2 C130.2 C131.2 C132.2 C137.2 C138.2 C139.2 C140.2 C141.2 C142.2 C143.2 C144.2 C145.2 C146.2 C147.2 C148.2 C149.2 C150.2 C151.2 C152.2 C153.2 C154.2 C155.2 C156.2 C157.2 C158.2 C159.2 C160.2 C161.2 C162.2 C163.2 C164.2 C165.2 C166.2 C170.2 C171.2 C172.2 C173.2 C178.2 C179.2 C180.2 C181.2 C182.2 C183.2 C184.2 C185.2 C186.2 C187.2 C188.2 C189.2 C190.2 C191.2 C192.2 C193.2 C194.2 C195.2 C196.2 C197.2 C198.2 C199.2 C200.2 C201.2 C202.2 C203.2 C204.2 C205.2 C206.2 C207.2 C276.2 C299.2 C305.2 C355.2 C356.2 C448.2 C463.2 C1737.2 C1747.2 R260.1 R261.1 R1452.2 R1481.2 R1482.2 U15.A3(VSS_MAIN_1) U15.A23(VSS_MAIN_2) U15.A31(VSS_MAIN_3) U15.A51(VSS_MAIN_4) U15.AA1(VSS_MAIN_5) U15.AA3(VSS_MAIN_6) U15.AA5(VSS_MAIN_7) U15.AA7(VSS_MAIN_8) U15.AA9(VSS_MAIN_9) U15.AA11(VSS_MAIN_10) U15.AA13(VSS_MAIN_11) U15.AA17(VSS_MAIN_12) U15.AA21(VSS_MAIN_13) U15.AA25(VSS_MAIN_14) U15.AA29(VSS_MAIN_15) U15.AA33(VSS_MAIN_16) U15.AA37(VSS_MAIN_17) U15.AA41(VSS_MAIN_18) U15.AA43(VSS_MAIN_19) U15.AA45(VSS_MAIN_20) U15.AA47(VSS_MAIN_21) U15.AA49(VSS_MAIN_22) U15.AA51(VSS_MAIN_23) U15.AA53(VSS_MAIN_24) U15.AB12(VSS_MAIN_25) U15.AB18(VSS_MAIN_26) U15.AB22(VSS_MAIN_27) U15.AB26(VSS_MAIN_28) U15.AB30(VSS_MAIN_29) U15.AB34(VSS_MAIN_30) U15.AB42(VSS_MAIN_31) U15.AC13(VSS_MAIN_32) U15.AC19(VSS_MAIN_33) U15.AC23(VSS_MAIN_34) U15.AC27(VSS_MAIN_35) U15.AC31(VSS_MAIN_36) U15.AC35(VSS_MAIN_37) U15.AC41(VSS_MAIN_38) U15.AD2(VSS_MAIN_39) U15.AD4(VSS_MAIN_40) U15.AD6(VSS_MAIN_41) U15.AD8(VSS_MAIN_42) U15.AD10(VSS_MAIN_43) U15.AD12(VSS_MAIN_44) U15.AD20(VSS_MAIN_45) U15.AD24(VSS_MAIN_46) U15.AD28(VSS_MAIN_47) U15.AD32(VSS_MAIN_48) U15.AD36(VSS_MAIN_49) U15.AD42(VSS_MAIN_50) U15.AD44(VSS_MAIN_51) U15.AD46(VSS_MAIN_52) U15.AD48(VSS_MAIN_53) U15.AD50(VSS_MAIN_54) U15.AD52(VSS_MAIN_55) U15.AE13(VSS_MAIN_56) U15.AE17(VSS_MAIN_57) U15.AE21(VSS_MAIN_58) U15.AE25(VSS_MAIN_59) U15.AE29(VSS_MAIN_60) U15.AE33(VSS_MAIN_61) U15.AE37(VSS_MAIN_62) U15.AE41(VSS_MAIN_63) U15.AF12(VSS_MAIN_64) U15.AF18(VSS_MAIN_65) U15.AF22(VSS_MAIN_66) U15.AF26(VSS_MAIN_67) U15.AF30(VSS_MAIN_68) U15.AF34(VSS_MAIN_69) U15.AF42(VSS_MAIN_70) U15.AG1(VSS_MAIN_71) U15.AG3(VSS_MAIN_72) U15.AG5(VSS_MAIN_73) U15.AG7(VSS_MAIN_74) U15.AG9(VSS_MAIN_75) U15.AG11(VSS_MAIN_76) U15.AG13(VSS_MAIN_77) U15.AG19(VSS_MAIN_78) U15.AG23(VSS_MAIN_79) U15.AG27(VSS_MAIN_80) U15.AG31(VSS_MAIN_81) U15.AG35(VSS_MAIN_82) U15.AG41(VSS_MAIN_83) U15.AG43(VSS_MAIN_84) U15.AG45(VSS_MAIN_85) U15.AG47(VSS_MAIN_86) U15.AG49(VSS_MAIN_87) U15.AG51(VSS_MAIN_88) U15.AG53(VSS_MAIN_89) U15.AH12(VSS_MAIN_90) U15.AH20(VSS_MAIN_91) U15.AH24(VSS_MAIN_92) U15.AH28(VSS_MAIN_93) U15.AH32(VSS_MAIN_94) U15.AH36(VSS_MAIN_95) U15.AH42(VSS_MAIN_96) U15.AJ13(VSS_MAIN_97) U15.AJ17(VSS_MAIN_98) U15.AJ21(VSS_MAIN_99) U15.AJ25(VSS_MAIN_100) U15.AJ29(VSS_MAIN_101) U15.AJ33(VSS_MAIN_102) U15.AJ37(VSS_MAIN_103) U15.AJ41(VSS_MAIN_104) U15.AK2(VSS_MAIN_105) U15.AK4(VSS_MAIN_106) U15.AK6(VSS_MAIN_107) U15.AK8(VSS_MAIN_108) U15.AK10(VSS_MAIN_109) U15.AK12(VSS_MAIN_110) U15.AK18(VSS_MAIN_111) U15.AK22(VSS_MAIN_112) U15.AK26(VSS_MAIN_113) U15.AK30(VSS_MAIN_114) U15.AK34(VSS_MAIN_115) U15.AK38(VSS_MAIN_116) U15.AK44(VSS_MAIN_117) U15.AK46(VSS_MAIN_118) U15.AK48(VSS_MAIN_119) U15.AK50(VSS_MAIN_120) U15.AK52(VSS_MAIN_121) U15.AL13(VSS_MAIN_122) U15.AL19(VSS_MAIN_123) U15.AL23(VSS_MAIN_124) U15.AL27(VSS_MAIN_125) U15.AL31(VSS_MAIN_126) U15.AL35(VSS_MAIN_127) U15.AL41(VSS_MAIN_128) U15.AM8(VSS_MAIN_129) U15.AM10(VREFL_ADC) U15.AM12(VSS_MAIN_130) U15.AM20(VSS_MAIN_131) U15.AM24(VSS_MAIN_132) U15.AM28(VSS_MAIN_133) U15.AM32(VSS_MAIN_134) U15.AM36(VSS_MAIN_135) U15.AM42(VSS_MAIN_136) U15.AM46(VSS_MAIN_137) U15.AN1(VSS_MAIN_138) U15.AN3(VSS_MAIN_139) U15.AN5(VSS_MAIN_140) U15.AN7(VSS_MAIN_141) U15.AN13(VSS_MAIN_142) U15.AN17(VSS_MAIN_143) U15.AN21(VSS_MAIN_144) U15.AN25(VSS_MAIN_145) U15.AN29(VSS_MAIN_146) U15.AN33(VSS_MAIN_147) U15.AN41(VSS_MAIN_148) U15.AN43(VSS_MAIN_149) U15.AN47(VSS_MAIN_150) U15.AN49(VSS_MAIN_151) U15.AN51(VSS_MAIN_152) U15.AN53(VSS_MAIN_153) U15.AP12(VSS_MAIN_154) U15.AP18(VSS_MAIN_155) U15.AP22(VSS_MAIN_156) U15.AP26(VSS_MAIN_157) U15.AP30(VSS_MAIN_158) U15.AP34(VSS_MAIN_159) U15.AR5(VSS_MAIN_160) U15.AR11(VSS_MAIN_161) U15.AR19(VSS_MAIN_162) U15.AR23(VSS_MAIN_163) U15.AR27(VSS_MAIN_164) U15.AR31(VSS_MAIN_165) U15.AR35(VSS_MAIN_166) U15.AR49(VSS_MAIN_167) U15.AT2(VSS_MAIN_168) U15.AT4(VSS_MAIN_169) U15.AT6(VSS_MAIN_170) U15.AT8(VSS_MAIN_171) U15.AT12(VSS_MAIN_172) U15.AT16(VSS_MAIN_173) U15.AT20(VSS_MAIN_174) U15.AT24(VSS_MAIN_175) U15.AT28(VSS_MAIN_176) U15.AT32(VSS_MAIN_177) U15.AT36(VSS_MAIN_178) U15.AT42(VSS_MAIN_179) U15.AT46(VSS_MAIN_180) U15.AT50(VSS_MAIN_181) U15.AT52(VSS_MAIN_182) U15.AU17(VSS_MAIN_183) U15.AU25(VSS_MAIN_184) U15.AU31(VSS_MAIN_185) U15.AU33(VSS_MAIN_186) U15.AU37(VSS_MAIN_187) U15.AV12(VSS_MAIN_188) U15.AV38(VSS_MAIN_189) U15.AV42(VSS_MAIN_190) U15.AW3(VSS_MAIN_191) U15.AW7(VSS_MAIN_192) U15.AW11(VSS_MAIN_193) U15.AW19(VSS_MAIN_194) U15.AW23(VSS_MAIN_195) U15.AW37(VSS_MAIN_196) U15.AW43(VSS_MAIN_197) U15.AW47(VSS_MAIN_198) U15.AW51(VSS_MAIN_199) U15.B6(VSS_MAIN_200) U15.B12(VSS_MAIN_201) U15.B14(VSS_MAIN_202) U15.B18(VSS_MAIN_203) U15.B28(VSS_MAIN_204) U15.B36(VSS_MAIN_205) U15.B46(VSS_MAIN_206) U15.BA13(VSS_MAIN_207) U15.BA15(VSS_MAIN_208) U15.BA17(VSS_MAIN_209) U15.BA19(VSS_MAIN_210) U15.BA21(VSS_MAIN_211) U15.BA23(VSS_MAIN_212) U15.BA25(VSS_MAIN_213) U15.BA27(VSS_MAIN_214) U15.BA29(VSS_MAIN_215) U15.BA31(VSS_MAIN_216) U15.BA33(VSS_MAIN_217) U15.BA35(VSS_MAIN_218) U15.BA37(VSS_MAIN_219) U15.BA39(VSS_MAIN_220) U15.BA41(VSS_MAIN_221) U15.BA45(VSS_MAIN_222) U15.BB2(VSS_MAIN_223) U15.BB6(VSS_MAIN_224) U15.BB10(VSS_MAIN_225) U15.BB14(VSS_MAIN_226) U15.BB16(VSS_MAIN_227) U15.BB18(VSS_MAIN_228) U15.BB20(VSS_MAIN_229) U15.BB22(VSS_MAIN_230) U15.BB24(VSS_MAIN_231) U15.BB26(VSS_MAIN_232) U15.BB28(VSS_MAIN_233) U15.BB30(VSS_MAIN_234) U15.BB32(VSS_MAIN_235) U15.BB34(VSS_MAIN_236) U15.BB36(VSS_MAIN_237) U15.BB38(VSS_MAIN_238) U15.BB40(VSS_MAIN_239) U15.BB48(VSS_MAIN_240) U15.BB52(VSS_MAIN_241) U15.BC11(VSS_MAIN_242) U15.BC13(VSS_MAIN_243) U15.BC15(VSS_MAIN_244) U15.BC17(VSS_MAIN_245) U15.BC19(VSS_MAIN_246) U15.BC21(VSS_MAIN_247) U15.BC23(VSS_MAIN_248) U15.BC25(VSS_MAIN_249) U15.BC27(VSS_MAIN_250) U15.BC29(VSS_MAIN_251) U15.BC31(VSS_MAIN_252) U15.BC33(VSS_MAIN_253) U15.BC35(VSS_MAIN_254) U15.BC37(VSS_MAIN_255) U15.BC39(VSS_MAIN_256) U15.BC41(VSS_MAIN_257) U15.BC43(VSS_MAIN_258) U15.BC49(TEST_MODE_SELECT) U15.BD14(VSS_MAIN_259) U15.BD16(VSS_MAIN_260) U15.BD18(VSS_MAIN_261) U15.BD20(VSS_MAIN_262) U15.BD22(VSS_MAIN_263) U15.BD24(VSS_MAIN_264) U15.BD26(VSS_MAIN_265) U15.BD48(VSS_MAIN_267) U15.BD50(VSS_MAIN_268) U15.BE3(VSS_MAIN_269) U15.BE7(VSS_MAIN_270) U15.BE9(VSS_MAIN_271) U15.BE45(VSS_MAIN_266) U15.BF4(VSS_MAIN_272) U15.BF26(VSS_MAIN_273) U15.BF28(VSS_MAIN_274) U15.BF30(VSS_MAIN_275) U15.BF32(VSS_MAIN_276) U15.BF34(VSS_MAIN_277) U15.BF36(VSS_MAIN_278) U15.BF38(VSS_MAIN_279) U15.BF40(VSS_MAIN_280) U15.BF42(VSS_MAIN_281) U15.BF44(VSS_MAIN_282) U15.BF52(VSS_MAIN_283) U15.BG7(VSS_MAIN_284) U15.BG11(VSS_MAIN_285) U15.BG13(VSS_MAIN_286) U15.BG15(VSS_MAIN_287) U15.BG17(VSS_MAIN_288) U15.BG19(VSS_MAIN_289) U15.BG21(VSS_MAIN_290) U15.BG23(VSS_MAIN_291) U15.BG47(VSS_MAIN_292) U15.BH4(VSS_MAIN_293) U15.BH22(VSS_MAIN_294) U15.BJ3(VSS_MAIN_295) U15.BJ5(VSS_MAIN_296) U15.BJ25(VSS_MAIN_297) U15.BJ27(VSS_MAIN_298) U15.BJ29(VSS_MAIN_299) U15.BJ31(VSS_MAIN_300) U15.BJ33(VSS_MAIN_301) U15.BJ35(VSS_MAIN_302) U15.BJ37(VSS_MAIN_303) U15.BJ39(VSS_MAIN_304) U15.BJ41(VSS_MAIN_305) U15.BJ43(VSS_MAIN_306) U15.BJ45(VSS_MAIN_307) U15.BJ47(VSS_MAIN_308) U15.BJ49(VSS_MAIN_309) U15.BJ51(VSS_MAIN_310) U15.BK6(VSS_MAIN_311) U15.BK8(VSS_MAIN_312) U15.BK10(VSS_MAIN_313) U15.BK12(VSS_MAIN_314) U15.BK14(VSS_MAIN_315) U15.BK16(VSS_MAIN_316) U15.BK18(VSS_MAIN_317) U15.BK20(VSS_MAIN_318) U15.BK22(VSS_MAIN_319) U15.BK46(VSS_MAIN_320) U15.BL1(VSS_MAIN_321) U15.BL21(VSS_MAIN_322) U15.BL53(VSS_MAIN_323) U15.BM10(VSS_MAIN_324) U15.BM46(VSS_MAIN_325) U15.BN3(VSS_MAIN_326) U15.BN21(VSS_MAIN_327) U15.C1(VSS_MAIN_328) U15.C9(VSS_MAIN_329) U15.C11(VSS_MAIN_330) U15.C15(VSS_MAIN_331) U15.C19(VSS_MAIN_332) U15.C21(VSS_MAIN_333) U15.C23(VSS_MAIN_334) U15.C29(VSS_MAIN_335) U15.C31(VSS_MAIN_336) U15.C33(VSS_MAIN_337) U15.C41(VSS_MAIN_338) U15.C43(VSS_MAIN_339) U15.C49(VSS_MAIN_340) U15.C53(VSS_MAIN_341) U15.D6(VSS_MAIN_342) U15.D16(VSS_MAIN_343) U15.D18(VSS_MAIN_344) U15.D24(VSS_MAIN_345) U15.D26(VSS_MAIN_346) U15.D28(VSS_MAIN_347) U15.D34(VSS_MAIN_348) U15.D36(VSS_MAIN_349) U15.D38(VSS_MAIN_350) U15.D40(VSS_MAIN_351) U15.E9(VSS_MAIN_352) U15.E19(VSS_MAIN_353) U15.E21(VSS_MAIN_354) U15.E47(VSS_MAIN_355) U15.F2(VSS_MAIN_356) U15.F4(VSS_MAIN_357) U15.F12(VSS_MAIN_358) U15.F24(VSS_MAIN_359) U15.F32(VSS_MAIN_360) U15.F36(VSS_MAIN_361) U15.F44(VSS_MAIN_362) U15.F50(VSS_MAIN_363) U15.F52(VSS_MAIN_364) U15.G5(VSS_MAIN_365) U15.G9(VSS_MAIN_366) U15.G15(VSS_MAIN_367) U15.G21(VSS_MAIN_368) U15.G23(VSS_MAIN_369) U15.G27(VSS_MAIN_370) U15.G33(VSS_MAIN_371) U15.G39(VSS_MAIN_372) U15.G49(VSS_MAIN_373) U15.J1(VSS_MAIN_374) U15.J3(VSS_MAIN_375) U15.J5(VSS_MAIN_376) U15.J7(VSS_MAIN_377) U15.J13(VSS_MAIN_378) U15.J15(VSS_MAIN_379) U15.J17(VSS_MAIN_380) U15.J19(VSS_MAIN_381) U15.J21(VSS_MAIN_382) U15.J23(VSS_MAIN_383) U15.J25(VSS_MAIN_384) U15.J29(VSS_MAIN_385) U15.J31(VSS_MAIN_386) U15.J35(VSS_MAIN_387) U15.J37(VSS_MAIN_388) U15.J41(VSS_MAIN_389) U15.J47(VSS_MAIN_390) U15.J49(VSS_MAIN_391) U15.J51(VSS_MAIN_392) U15.J53(VSS_MAIN_393) U15.K8(VSS_MAIN_394) U15.K12(VSS_MAIN_395) U15.K14(VSS_MAIN_396) U15.K16(VSS_MAIN_397) U15.K18(VSS_MAIN_398) U15.K20(VSS_MAIN_399) U15.K22(VSS_MAIN_400) U15.K24(VSS_MAIN_401) U15.K26(VSS_MAIN_402) U15.K28(VSS_MAIN_403) U15.K30(VSS_MAIN_404) U15.K32(VSS_MAIN_405) U15.K34(VSS_MAIN_406) U15.K36(VSS_MAIN_407) U15.K38(VSS_MAIN_408) U15.K40(VSS_MAIN_409) U15.K42(VSS_MAIN_410) U15.K46(VSS_MAIN_411) U15.L11(VSS_MAIN_412) U15.L13(VSS_MAIN_413) U15.L15(VSS_MAIN_414) U15.L17(VSS_MAIN_415) U15.L19(VSS_MAIN_416) U15.L21(VSS_MAIN_417) U15.L23(VSS_MAIN_418) U15.L25(VSS_MAIN_419) U15.L27(VSS_MAIN_420) U15.L29(VSS_MAIN_421) U15.L31(VSS_MAIN_422) U15.L33(VSS_MAIN_423) U15.L35(VSS_MAIN_424) U15.L37(VSS_MAIN_425) U15.L39(VSS_MAIN_426) U15.L41(VSS_MAIN_427) U15.L43(VSS_MAIN_428) U15.M2(VSS_MAIN_429) U15.M4(VSS_MAIN_430) U15.M6(VSS_MAIN_431) U15.M8(VSS_MAIN_432) U15.M10(VSS_MAIN_433) U15.M44(VSS_MAIN_434) U15.M46(VSS_MAIN_435) U15.M48(VSS_MAIN_436) U15.M50(VSS_MAIN_437) U15.M52(VSS_MAIN_438) U15.N13(VSS_MAIN_439) U15.N41(VSS_MAIN_440) U15.P12(VSS_MAIN_441) U15.P42(VSS_MAIN_442) U15.R1(VSS_MAIN_443) U15.R3(VSS_MAIN_444) U15.R5(VSS_MAIN_445) U15.R7(VSS_MAIN_446) U15.R9(VSS_MAIN_447) U15.R11(VSS_MAIN_448) U15.R15(VSS_MAIN_449) U15.R17(VSS_MAIN_450) U15.R19(VSS_MAIN_451) U15.R21(VSS_MAIN_452) U15.R23(VSS_MAIN_453) U15.R25(VSS_MAIN_454) U15.R27(VSS_MAIN_455) U15.R29(VSS_MAIN_456) U15.R31(VSS_MAIN_457) U15.R33(VSS_MAIN_458) U15.R35(VSS_MAIN_459) U15.R37(VSS_MAIN_460) U15.R39(VSS_MAIN_461) U15.R43(VSS_MAIN_462) U15.R45(VSS_MAIN_463) U15.R47(VSS_MAIN_464) U15.R49(VSS_MAIN_465) U15.R51(VSS_MAIN_466) U15.R53(VSS_MAIN_467) U15.T12(VSS_MAIN_468) U15.T16(VSS_MAIN_469) U15.T20(VSS_MAIN_470) U15.T24(VSS_MAIN_471) U15.T28(VSS_MAIN_472) U15.T32(VSS_MAIN_473) U15.T36(VSS_MAIN_474) U15.T42(VSS_MAIN_475) U15.U17(VSS_MAIN_476) U15.U21(VSS_MAIN_477) U15.U33(VSS_MAIN_478) U15.U37(VSS_MAIN_479) U15.V2(VSS_MAIN_480) U15.V4(VSS_MAIN_481) U15.V6(VSS_MAIN_482) U15.V8(VSS_MAIN_483) U15.V10(VSS_MAIN_484) U15.V12(VSS_MAIN_485) U15.V18(VSS_MAIN_486) U15.V22(VSS_MAIN_487) U15.V30(VSS_MAIN_488) U15.V34(VSS_MAIN_489) U15.V42(VSS_MAIN_490) U15.V44(VSS_MAIN_491) U15.V46(VSS_MAIN_492) U15.V48(VSS_MAIN_493) U15.V50(VSS_MAIN_494) U15.V52(VSS_MAIN_495) U15.W19(VSS_MAIN_496) U15.W23(VSS_MAIN_497) U15.W27(VSS_MAIN_498) U15.W31(VSS_MAIN_499) U15.W35(VSS_MAIN_500) U15.Y12(VSS_MAIN_501) U15.Y20(VSS_MAIN_502) U15.Y24(VSS_MAIN_503) U15.Y28(VSS_MAIN_504) U15.Y32(VSS_MAIN_505) U15.Y36(VSS_MAIN_506) U15.Y42(VSS_MAIN_507) U17.A3(VSS) U17.A10(VSS) U17.AB3(VSS) U17.AB5(VSS) U17.AB8(VSS) U17.AB10(VSS) U17.C1(VSS) U17.C5(VSS) U17.C8(VSS) U17.C12(VSS) U17.D2(VSS) U17.D4(VSS) U17.D9(VSS) U17.D11(VSS) U17.E1(VSS) U17.E5(VSS) U17.E8(VSS) U17.E12(VSS) U17.G1(VSS) U17.G3(VSS) U17.G5(VSS) U17.G8(VSS) U17.G10(VSS) U17.G12(VSS) U17.J1(VSS) U17.J3(VSS) U17.J10(VSS) U17.J12(VSS) U17.K2(VSS) U17.K4(VSS) U17.K9(VSS) U17.K11(VSS) U17.N2(VSS) U17.N4(VSS) U17.N9(VSS) U17.N11(VSS) U17.P1(VSS) U17.P3(VSS) U17.P10(VSS) U17.P12(VSS) U17.T1(VSS) U17.T3(VSS) U17.T5(VSS) U17.T8(VSS) U17.T10(VSS) U17.T12(VSS) U17.V1(VSS) U17.V5(VSS) U17.V8(VSS) U17.V12(VSS) U17.W2(VSS) U17.W4(VSS) U17.W9(VSS) U17.W11(VSS) U17.Y1(VSS) U17.Y5(VSS) U17.Y8(VSS) U17.Y12(VSS) U18.A3(VSS) U18.A10(VSS) U18.AB3(VSS) U18.AB5(VSS) U18.AB8(VSS) U18.AB10(VSS) U18.C1(VSS) U18.C5(VSS) U18.C8(VSS) U18.C12(VSS) U18.D2(VSS) U18.D4(VSS) U18.D9(VSS) U18.D11(VSS) U18.E1(VSS) U18.E5(VSS) U18.E8(VSS) U18.E12(VSS) U18.G1(VSS) U18.G3(VSS) U18.G5(VSS) U18.G8(VSS) U18.G10(VSS) U18.G12(VSS) U18.J1(VSS) U18.J3(VSS) U18.J10(VSS) U18.J12(VSS) U18.K2(VSS) U18.K4(VSS) U18.K9(VSS) U18.K11(VSS) U18.N2(VSS) U18.N4(VSS) U18.N9(VSS) U18.N11(VSS) U18.P1(VSS) U18.P3(VSS) U18.P10(VSS) U18.P12(VSS) U18.T1(VSS) U18.T3(VSS) U18.T5(VSS) U18.T8(VSS) U18.T10(VSS) U18.T12(VSS) U18.V1(VSS) U18.V5(VSS) U18.V8(VSS) U18.V12(VSS) U18.W2(VSS) U18.W4(VSS) U18.W9(VSS) U18.W11(VSS) U18.Y1(VSS) U18.Y5(VSS) U18.Y8(VSS) U18.Y12(VSS) U64.3(GND) U216.2(A) U216.3(GND) ; also on sheet 2 5 6 10 11 12 18 19 20 21 22 23 24 25 26 27 28 29 30 31 32
VCC_1V8: C63.1 C129.1 C130.1 C131.1 C132.1 C170.1 C171.1 C172.1 C173.1 C276.1 R60.1 R62.1 R379.1 R380.1 U17.F1(VDD1) U17.F12(VDD1) U17.G4(VDD1) U17.G9(VDD1) U17.T4(VDD1) U17.T9(VDD1) U17.U1(VDD1) U17.U12(VDD1) U18.F1(VDD1) U18.F12(VDD1) U18.G4(VDD1) U18.G9(VDD1) U18.T4(VDD1) U18.T9(VDD1) U18.U1(VDD1) U18.U12(VDD1) ; also on sheet 2 6 10 11 12 18 19 21 24 27 28 31
VCC_DDRIO0: C47.1 C137.1 C138.1 C139.1 C140.1 C141.1 C142.1 C143.1 C144.1 C145.1 C146.1 C147.1 C148.1 C149.1 C150.1 C151.1 C152.1 C153.1 C154.1 C155.1 C156.1 C157.1 C158.1 C159.1 C160.1 C161.1 C162.1 C163.1 C164.1 C165.1 C166.1 C305.1 C448.1 C463.1 R77.2 R89.2 R276.2 R281.2 U17.A4(VDD2) U17.A9(VDD2) U17.AA3(VDDQ) U17.AA5(VDDQ) U17.AA8(VDDQ) U17.AA10(VDDQ) U17.AB4(VDD2) U17.AB9(VDD2) U17.B3(VDDQ) U17.B5(VDDQ) U17.B8(VDDQ) U17.B10(VDDQ) U17.D1(VDDQ) U17.D5(VDDQ) U17.D8(VDDQ) U17.D12(VDDQ) U17.F3(VDDQ) U17.F5(VDD2) U17.F8(VDD2) U17.F10(VDDQ) U17.H1(VDD2) U17.H5(VDD2) U17.H8(VDD2) U17.H12(VDD2) U17.K1(VDD2) U17.K3(VDD2) U17.K10(VDD2) U17.K12(VDD2) U17.N1(VDD2) U17.N3(VDD2) U17.N10(VDD2) U17.N12(VDD2) U17.R1(VDD2) U17.R5(VDD2) U17.R8(VDD2) U17.R12(VDD2) U17.U3(VDDQ) U17.U5(VDD2) U17.U8(VDD2) U17.U10(VDDQ) U17.W1(VDDQ) U17.W5(VDDQ) U17.W8(VDDQ) U17.W12(VDDQ) ; also on sheet 6 12
VCC_DDRIO1: C56.1 C178.1 C179.1 C180.1 C181.1 C182.1 C183.1 C184.1 C185.1 C186.1 C187.1 C188.1 C189.1 C190.1 C191.1 C192.1 C193.1 C194.1 C195.1 C196.1 C197.1 C198.1 C199.1 C200.1 C201.1 C202.1 C203.1 C204.1 C205.1 C206.1 C207.1 C299.1 C355.1 C356.1 R75.2 R88.2 R248.2 R252.2 U18.A4(VDD2) U18.A9(VDD2) U18.AA3(VDDQ) U18.AA5(VDDQ) U18.AA8(VDDQ) U18.AA10(VDDQ) U18.AB4(VDD2) U18.AB9(VDD2) U18.B3(VDDQ) U18.B5(VDDQ) U18.B8(VDDQ) U18.B10(VDDQ) U18.D1(VDDQ) U18.D5(VDDQ) U18.D8(VDDQ) U18.D12(VDDQ) U18.F3(VDDQ) U18.F5(VDD2) U18.F8(VDD2) U18.F10(VDDQ) U18.H1(VDD2) U18.H5(VDD2) U18.H8(VDD2) U18.H12(VDD2) U18.K1(VDD2) U18.K3(VDD2) U18.K10(VDD2) U18.K12(VDD2) U18.N1(VDD2) U18.N3(VDD2) U18.N10(VDD2) U18.N12(VDD2) U18.R1(VDD2) U18.R5(VDD2) U18.R8(VDD2) U18.R12(VDD2) U18.U3(VDDQ) U18.U5(VDD2) U18.U8(VDD2) U18.U10(VDDQ) U18.W1(VDDQ) U18.W5(VDDQ) U18.W8(VDDQ) U18.W12(VDDQ) ; also on sheet 11 12
VCC_EXT_1V8: C1747.1 R1469.2 U216.5(VCC) ; also on sheet 2 5 6 10 29 30
VCC_SCU_1V8: C1737.1 R239.1 R240.1 R1453.2 R1468.1 U64.8(VCC) ; also on sheet 6 11 12 19 20 21
VCC_SNVS_LDO_1V8: R233.1 ; also on sheet 12
VSS_SCU_XTAL: U15.BK48(VSS_MAIN_508) U15.BM48(VSS_MAIN_509) U15.BM50(VSS_MAIN_510) U15.BN51(VSS_MAIN_511) ; also on sheet 12
ANA_TEST_OUT0_N: R1483.2 TP17.1(Pin1) U15.BH52(ANA_TEST_OUT0_N)
ANA_TEST_OUT0_P: R1483.1 TP18.1(Pin1) U15.BG53(ANA_TEST_OUT0_P)
ANA_TEST_OUT1_N: R1484.2 TP28.1(Pin1) U15.BD2(ANA_TEST_OUT1_N)
ANA_TEST_OUT1_P: R1484.1 TP24.1(Pin1) U15.BE1(ANA_TEST_OUT1_P)
AUD_DET_1V8(SCU_GPIO0_03): U15.BB46(SCU_GPIO0_03) ; also on sheet 27
BB_ARD_MIK_UART3_RX: U15.AR47(M40_GPIO0_00) ; also on sheet 2
BB_ARD_MIK_UART3_TX: U15.AU53(M40_GPIO0_01) ; also on sheet 2
BB_AUD_PWR_PWM(GPT1_COMPARE): U15.BA51(GPT1_COMPARE) ; also on sheet 2
BB_CAN0_RX: U15.C5(FLEXCAN0_RX) ; also on sheet 2
BB_CAN0_TX: U15.H6(FLEXCAN0_TX) ; also on sheet 2
BB_CAN1_RX: U15.E5(FLEXCAN1_RX) ; also on sheet 2
BB_CAN1_TX: U15.G7(FLEXCAN1_TX) ; also on sheet 2
BB_CAN2_RX: U15.C3(FLEXCAN2_RX) ; also on sheet 2
BB_CAN2_TX: U15.E7(FLEXCAN2_TX) ; also on sheet 2
BB_ESAI0_FSR: U15.AW9(ESAI0_FSR) ; also on sheet 2
BB_ESAI0_FST: U15.BG9(ESAI0_FST) ; also on sheet 2
BB_ESAI0_SCKR: U15.BB8(ESAI0_SCKR) ; also on sheet 2
BB_ESAI0_SCKT: U15.AY8(ESAI0_SCKT) ; also on sheet 2
BB_ESAI0_TX0: U15.BA9(ESAI0_TX0) ; also on sheet 2
BB_ESAI0_TX1: U15.BA7(ESAI0_TX1) ; also on sheet 2
BB_ESAI0_TX2_RX3: U15.AU9(ESAI0_TX2_RX3) ; also on sheet 2
BB_ESAI0_TX3_RX2: U15.BC5(ESAI0_TX3_RX2) ; also on sheet 2
BB_ESAI0_TX4_RX1: U15.AV8(ESAI0_TX4_RX1) ; also on sheet 2
BB_ESAI0_TX5_RX0: U15.AU7(ESAI0_TX5_RX0) ; also on sheet 2
BB_ESAI1_FSR: U15.BE11(ESAI1_FSR) ; also on sheet 2
BB_ESAI1_FST: U15.BF12(ESAI1_FST) ; also on sheet 2
BB_ESAI1_RX0: U15.AT10(ESAI1_TX5_RX0) ; also on sheet 2
BB_ESAI1_RX1: U15.AY12(ESAI1_TX4_RX1) ; also on sheet 2
BB_ESAI1_SCKR: U15.BD12(ESAI1_SCKR) ; also on sheet 2
BB_ESAI1_SCKT: U15.AY10(ESAI1_SCKT) ; also on sheet 2
BB_ESAI1_TX0: U15.BF10(ESAI1_TX0) ; also on sheet 2
BB_ESAI1_TX1: U15.BA11(ESAI1_TX1) ; also on sheet 2
BB_ESAI1_TX2: U15.AU11(ESAI1_TX2_RX3) ; also on sheet 2
BB_ESAI1_TX3: U15.AV10(ESAI1_TX3_RX2) ; also on sheet 2
BB_EXP_INT_1V8(SCU_GPIO0_06): U15.BG49(SCU_GPIO0_06) ; also on sheet 2
BB_GPIO1(SPDIF0_EXT_CLK): U15.BD6(SPDIF0_EXT_CLK) ; also on sheet 2
BB_GPIO_1V8(ADC_IN0): U15.AP10(ADC_IN0) ; also on sheet 2
BB_IOEXP_CAN_INT_B(GPT1_CLK): U15.BA53(GPT1_CLK) ; also on sheet 2
BB_IOEXP_INT_B(GPT1_CAPTURE): U15.AY50(GPT1_CAPTURE) ; also on sheet 2
BB_M41_I2C0_1V8_SCL: R380.2 U15.AR45(M41_I2C0_SCL) ; also on sheet 2
BB_M41_I2C0_1V8_SDA: R379.2 U15.AU49(M41_I2C0_SDA) ; also on sheet 2
BB_MCLK_IN(MCLK_IN0): U15.BC3(MCLK_IN0) ; also on sheet 2
BB_MCLKIN1(SPDIF0_RX): U15.BC7(SPDIF0_RX) ; also on sheet 2
BB_MCLKOUT1(SPDIF0_TX): U15.BC9(SPDIF0_TX) ; also on sheet 2
BB_MKBUS_INT_1V8(SCU_GPIO0_04): U15.BC47(SCU_GPIO0_04) ; also on sheet 2
BB_MLB_CLK: U15.D2(MLB_CLK) ; also on sheet 2
BB_MLB_CLK_N: U15.E33(MLB_CLK_N) ; also on sheet 2
BB_MLB_CLK_P: U15.D32(MLB_CLK_P) ; also on sheet 2
BB_MLB_DATA: U15.E3(MLB_DATA) ; also on sheet 2
BB_MLB_DATA_N: U15.E35(MLB_DATA_N) ; also on sheet 2
BB_MLB_DATA_P: U15.F34(MLB_DATA_P) ; also on sheet 2
BB_MLB_SIG: U15.E1(MLB_SIG) ; also on sheet 2
BB_MLB_SIG_N: U15.E31(MLB_SIG_N) ; also on sheet 2
BB_MLB_SIG_P: U15.D30(MLB_SIG_P) ; also on sheet 2
BB_RST_1V8_B(SCU_GPIO0_01): U64.7(2Y0) ; also on sheet 20
BB_SIM_CLK: U15.AL45(SIM0_CLK) ; also on sheet 2
BB_SIM_INT_B: U15.AP46(SIM0_GPIO0_00) ; also on sheet 2
BB_SIM_IO: U15.AN45(SIM0_IO) ; also on sheet 2
BB_SIM_PD: U15.AL43(SIM0_PD) ; also on sheet 2
BB_SIM_POWER_EN: U15.AT48(SIM0_POWER_EN) ; also on sheet 2
BB_SIM_RST: U15.AP48(SIM0_RST) ; also on sheet 2
BB_SPI0_CS0: U15.BC1(SPI0_CS0) ; also on sheet 2
BB_SPI0_MISO: U15.BA5(SPI0_SDI) ; also on sheet 2
BB_SPI0_MOSI: U15.AY6(SPI0_SDO) ; also on sheet 2
BB_SPI0_SCLK: U15.BB4(SPI0_SCK) ; also on sheet 2
BB_SPI1_CLK(ADC_IN3): U15.AR9(ADC_IN3) ; also on sheet 2
BB_SPI1_CS0(ADC_IN6): U15.AL9(ADC_IN6) ; also on sheet 2
BB_SPI1_CS1(ADC_IN7): U15.AP6(ADC_IN7) ; also on sheet 2
BB_SPI1_INT_1V8(SCU_GPIO0_05): U15.AY44(SCU_GPIO0_05) ; also on sheet 2
BB_SPI1_SDI(ADC_IN5): U15.AR7(ADC_IN5) ; also on sheet 2
BB_SPI1_SDO(ADC_IN4): U15.AN9(ADC_IN4) ; also on sheet 2
BB_SPI2_CS0: U15.AW1(SPI2_CS0) ; also on sheet 2
BB_SPI2_MISO: U15.AY4(SPI2_SDI) ; also on sheet 2
BB_SPI2_MOSI: U15.BA1(SPI2_SDO) ; also on sheet 2
BB_SPI2_SCLK: U15.AW5(SPI2_SCK) ; also on sheet 2
BB_SPI3_CS0: U15.BG5(SPI3_CS0) ; also on sheet 2
BB_SPI3_CS1: U15.BD8(SPI3_CS1) ; also on sheet 2
BB_SPI3_INT_1V8(ADC_IN1): U15.AN11(ADC_IN1) ; also on sheet 2
BB_SPI3_MISO: U15.BE5(SPI3_SDI) ; also on sheet 2
BB_SPI3_MOSI: U15.BF2(SPI3_SDO) ; also on sheet 2
BB_SPI3_SCLK: U15.BF6(SPI3_SCK) ; also on sheet 2
BB_TAMPER_IN0: U15.BE41(SNVS_TAMPER_IN0) ; also on sheet 2
BB_TAMPER_IN1: U15.BE43(SNVS_TAMPER_IN1) ; also on sheet 2
BB_TAMPER_OUT0: U15.BD46(SNVS_TAMPER_OUT0) ; also on sheet 2
BB_TAMPER_OUT1: U15.BD42(SNVS_TAMPER_OUT1) ; also on sheet 2
BB_UART2_RX: U15.AU45(UART0_RTS_B) ; also on sheet 2
BB_UART2_TX: U15.AW49(UART0_CTS_B) ; also on sheet 2
BB_UART4_RX_AUDIN: U15.AP44(M41_GPIO0_00) ; also on sheet 2
BB_UART4_TX_AUDIN: U15.AU47(M41_GPIO0_01) ; also on sheet 2
BB_USB_OTG1_FLT_B: R1469.1 U216.1(~{OE}) ; also on sheet 2
BT_SAI0_RXD(SAI1_RXFS): U15.AU3(SAI1_RXFS) ; also on sheet 26
BT_SAI0_TXC(SPI0_CS1): U15.BA3(SPI0_CS1) ; also on sheet 26
BT_SAI0_TXD(SAI1_RXC): U15.AV6(SAI1_RXC) ; also on sheet 26
BT_SAI0_TXFS(SPI2_CS1): U15.AY2(SPI2_CS1) ; also on sheet 26
BT_UART1_CTS: U15.AV46(UART1_CTS_B) ; also on sheet 26
BT_UART1_RTS: U15.AR43(UART1_RTS_B) ; also on sheet 26
BT_UART1_RX: U15.AT44(UART1_RX) ; also on sheet 26
BT_UART1_TX: U15.AY48(UART1_TX) ; also on sheet 26
CPU_RST_1V8_B: U15.BC53(SCU_PMIC_MEMC_ON) ; also on sheet 20
DDR_CH0_ATO: U15.AF46(DDR_CH0_ATO)
DDR_CH0_CA0_A: U15.U51(DDR_CH0_DCF11) U17.H2(CA0_A)
DDR_CH0_CA0_B: U15.AE51(DDR_CH0_DCF27) U17.R2(CA0_B)
DDR_CH0_CA1_A: U15.U53(DDR_CH0_DCF16) U17.J2(CA1_A)
DDR_CH0_CA1_B: U15.AE53(DDR_CH0_DCF32) U17.P2(CA1_B)
DDR_CH0_CA2_A: U15.U47(DDR_CH0_DCF00) U17.H9(CA2_A)
DDR_CH0_CA2_B: U15.AF48(DDR_CH0_DCF33) U17.R9(CA2_B)
DDR_CH0_CA3_A: U15.T48(DDR_CH0_DCF08) U17.H10(CA3_A)
DDR_CH0_CA3_B: U15.AE47(DDR_CH0_DCF26) U17.R10(CA3_B)
DDR_CH0_CA4_A: U15.W47(DDR_CH0_DCF01) U17.H11(CA4_A)
DDR_CH0_CA4_B: U15.AC47(DDR_CH0_DCF17) U17.R11(CA4_B)
DDR_CH0_CA5_A: U15.Y46(DDR_CH0_DCF03) U17.J11(CA5_A)
DDR_CH0_CA5_B: U15.AB46(DDR_CH0_DCF19) U17.P11(CA5_B)
DDR_CH0_CK0_N: U15.Y50(DDR_CH0_CK0_N) U17.J9(CK_c_A)
DDR_CH0_CK0_P: U15.W49(DDR_CH0_CK0_P) U17.J8(CK_t_A)
DDR_CH0_CK1_N: U15.AB50(DDR_CH0_CK1_N) U17.P9(CK_c_B)
DDR_CH0_CK1_P: U15.AC49(DDR_CH0_CK1_P) U17.P8(CK_t_B)
DDR_CH0_CKE0_A: U15.W53(DDR_CH0_DCF14) U17.J4(CKE0_A)
DDR_CH0_CKE0_B: U15.AC53(DDR_CH0_DCF30) U17.P4(CKE0_B)
DDR_CH0_CKE1_A: U15.Y52(DDR_CH0_DCF15) U17.J5(CKE1_A)
DDR_CH0_CKE1_B: U15.AB52(DDR_CH0_DCF31) U17.P5(CKE1_B)
DDR_CH0_CS0_A: U15.T50(DDR_CH0_DCF10) U17.H4(CS0_A)
DDR_CH0_CS0_B: U15.AF50(DDR_CH0_DCF28) U17.R4(CS0_B)
DDR_CH0_CS1_A: U15.U49(DDR_CH0_DCF12) U17.H3(CS1_A)
DDR_CH0_CS1_B: U15.AE49(DDR_CH0_DCF29) U17.R3(CS1_B)
DDR_CH0_DM0: U15.H52(DDR_CH0_DM0) U17.C10(DMI1_A)
DDR_CH0_DM1: U15.N47(DDR_CH0_DM1) U17.C3(DMI0_A)
DDR_CH0_DM2: U15.AJ47(DDR_CH0_DM2) U17.Y3(DMI0_B)
DDR_CH0_DM3: U15.AP52(DDR_CH0_DM3) U17.Y10(DMI1_B)
DDR_CH0_DQ0: U15.P44(DDR_CH0_DQ00) U17.F9(DQ12_A)
DDR_CH0_DQ1: U15.N45(DDR_CH0_DQ01) U17.E9(DQ13_A)
DDR_CH0_DQ2: U15.L47(DDR_CH0_DQ02) U17.B9(DQ15_A)
DDR_CH0_DQ3: U15.K48(DDR_CH0_DQ03) U17.F11(DQ11_A)
DDR_CH0_DQ4: U15.H50(DDR_CH0_DQ04) U17.E11(DQ10_A)
DDR_CH0_DQ5: U15.G53(DDR_CH0_DQ05) U17.B11(DQ8_A)
DDR_CH0_DQ6: U15.G51(DDR_CH0_DQ06) U17.C11(DQ9_A)
DDR_CH0_DQ7: U15.N43(DDR_CH0_DQ07) U17.C9(DQ14_A)
DDR_CH0_DQ8: U15.L49(DDR_CH0_DQ08) U17.C4(DQ6_A)
DDR_CH0_DQ9: U15.K50(DDR_CH0_DQ09) U17.B4(DQ7_A)
DDR_CH0_DQ10: U15.N51(DDR_CH0_DQ10) U17.B2(DQ0_A)
DDR_CH0_DQ11: U15.L51(DDR_CH0_DQ11) U17.C2(DQ1_A)
DDR_CH0_DQ12: U15.P46(DDR_CH0_DQ12) U17.E4(DQ5_A)
DDR_CH0_DQ13: U15.N49(DDR_CH0_DQ13) U17.F2(DQ3_A)
DDR_CH0_DQ14: U15.P50(DDR_CH0_DQ14) U17.E2(DQ2_A)
DDR_CH0_DQ15: U15.P48(DDR_CH0_DQ15) U17.F4(DQ4_A)
DDR_CH0_DQ16: U15.AM50(DDR_CH0_DQ16) U17.AA4(DQ7_B)
DDR_CH0_DQ17: U15.AL49(DDR_CH0_DQ17) U17.Y4(DQ6_B)
DDR_CH0_DQ18: U15.AL51(DDR_CH0_DQ18) U17.AA2(DQ0_B)
DDR_CH0_DQ19: U15.AJ51(DDR_CH0_DQ19) U17.Y2(DQ1_B)
DDR_CH0_DQ20: U15.AJ49(DDR_CH0_DQ20) U17.U2(DQ3_B)
DDR_CH0_DQ21: U15.AH46(DDR_CH0_DQ21) U17.V4(DQ5_B)
DDR_CH0_DQ22: U15.AH48(DDR_CH0_DQ22) U17.U4(DQ4_B)
DDR_CH0_DQ23: U15.AH50(DDR_CH0_DQ23) U17.V2(DQ2_B)
DDR_CH0_DQ24: U15.AJ45(DDR_CH0_DQ24) U17.V9(DQ13_B)
DDR_CH0_DQ25: U15.AH44(DDR_CH0_DQ25) U17.U9(DQ12_B)
DDR_CH0_DQ26: U15.AM48(DDR_CH0_DQ26) U17.U11(DQ11_B)
DDR_CH0_DQ27: U15.AL47(DDR_CH0_DQ27) U17.AA9(DQ15_B)
DDR_CH0_DQ28: U15.AR53(DDR_CH0_DQ28) U17.AA11(DQ8_B)
DDR_CH0_DQ29: U15.AP50(DDR_CH0_DQ29) U17.V11(DQ10_B)
DDR_CH0_DQ30: U15.AJ43(DDR_CH0_DQ30) U17.Y9(DQ14_B)
DDR_CH0_DQ31: U15.AR51(DDR_CH0_DQ31) U17.Y11(DQ9_B)
DDR_CH0_DQS0_N: U15.L53(DDR_CH0_DQS0_N) U17.E10(DQS1_c_A)
DDR_CH0_DQS0_P: U15.K52(DDR_CH0_DQS0_P) U17.D10(DQS1_t_A)
DDR_CH0_DQS1_N: U15.P52(DDR_CH0_DQS1_N) U17.E3(DQS0_c_A)
DDR_CH0_DQS1_P: U15.N53(DDR_CH0_DQS1_P) U17.D3(DQS0_t_A)
DDR_CH0_DQS2_N: U15.AH52(DDR_CH0_DQS2_N) U17.V3(DQS0_c_B)
DDR_CH0_DQS2_P: U15.AJ53(DDR_CH0_DQS2_P) U17.W3(DQS0_t_B)
DDR_CH0_DQS3_N: U15.AL53(DDR_CH0_DQS3_N) U17.V10(DQS1_c_B)
DDR_CH0_DQS3_P: U15.AM52(DDR_CH0_DQS3_P) U17.W10(DQS1_t_B)
DDR_CH0_DTO0: U15.U45(DDR_CH0_DTO0)
DDR_CH0_DTO1: U15.T44(DDR_CH0_DTO1)
DDR_CH0_ODT_A: R89.1 U17.G2(ODT_CA_A)
DDR_CH0_ODT_B: R77.1 U17.T2(ODT_CA_B)
DDR_CH0_RST_B: R1481.1 U15.AB48(DDR_CH0_DCF18) U17.T11(RESET_N)
DDR_CH0_VREF: U15.U43(DDR_CH0_VREF)
DDR_CH0_ZQ: R260.2 U15.AF44(DDR_CH0_ZQ)
DDR_CH1_ATO: U15.AF8(DDR_CH1_ATO)
DDR_CH1_CA0_A: U15.U3(DDR_CH1_DCF11) U18.R2(CA0_B)
DDR_CH1_CA0_B: U15.AE3(DDR_CH1_DCF27) U18.H2(CA0_A)
DDR_CH1_CA1_A: U15.U1(DDR_CH1_DCF16) U18.P2(CA1_B)
DDR_CH1_CA1_B: U15.AE1(DDR_CH1_DCF32) U18.J2(CA1_A)
DDR_CH1_CA2_A: U15.U7(DDR_CH1_DCF00) U18.R9(CA2_B)
DDR_CH1_CA2_B: U15.AF6(DDR_CH1_DCF33) U18.H9(CA2_A)
DDR_CH1_CA3_A: U15.T6(DDR_CH1_DCF08) U18.R10(CA3_B)
DDR_CH1_CA3_B: U15.AE7(DDR_CH1_DCF26) U18.H10(CA3_A)
DDR_CH1_CA4_A: U15.W7(DDR_CH1_DCF01) U18.R11(CA4_B)
DDR_CH1_CA4_B: U15.AC7(DDR_CH1_DCF17) U18.H11(CA4_A)
DDR_CH1_CA5_A: U15.Y8(DDR_CH1_DCF03) U18.P11(CA5_B)
DDR_CH1_CA5_B: U15.AB8(DDR_CH1_DCF19) U18.J11(CA5_A)
DDR_CH1_CK0_N: U15.Y4(DDR_CH1_CK0_N) U18.P9(CK_c_B)
DDR_CH1_CK0_P: U15.W5(DDR_CH1_CK0_P) U18.P8(CK_t_B)
DDR_CH1_CK1_N: U15.AB4(DDR_CH1_CK1_N) U18.J9(CK_c_A)
DDR_CH1_CK1_P: U15.AC5(DDR_CH1_CK1_P) U18.J8(CK_t_A)
DDR_CH1_CKE0_A: U15.W1(DDR_CH1_DCF14) U18.P4(CKE0_B)
DDR_CH1_CKE0_B: U15.AC1(DDR_CH1_DCF30) U18.J4(CKE0_A)
DDR_CH1_CKE1_A: U15.Y2(DDR_CH1_DCF15) U18.P5(CKE1_B)
DDR_CH1_CKE1_B: U15.AB2(DDR_CH1_DCF31) U18.J5(CKE1_A)
DDR_CH1_CS0_A: U15.T4(DDR_CH1_DCF10) U18.R4(CS0_B)
DDR_CH1_CS0_B: U15.AF4(DDR_CH1_DCF28) U18.H4(CS0_A)
DDR_CH1_CS1_A: U15.U5(DDR_CH1_DCF12) U18.R3(CS1_B)
DDR_CH1_CS1_B: U15.AE5(DDR_CH1_DCF29) U18.H3(CS1_A)
DDR_CH1_DM0: U15.H2(DDR_CH1_DM0) U18.Y10(DMI1_B)
DDR_CH1_DM1: U15.N7(DDR_CH1_DM1) U18.Y3(DMI0_B)
DDR_CH1_DM2: U15.AJ7(DDR_CH1_DM2) U18.C3(DMI0_A)
DDR_CH1_DM3: U15.AP2(DDR_CH1_DM3) U18.C10(DMI1_A)
DDR_CH1_DQ0: U15.P10(DDR_CH1_DQ00) U18.U9(DQ12_B)
DDR_CH1_DQ1: U15.N9(DDR_CH1_DQ01) U18.V9(DQ13_B)
DDR_CH1_DQ2: U15.L7(DDR_CH1_DQ02) U18.AA9(DQ15_B)
DDR_CH1_DQ3: U15.K6(DDR_CH1_DQ03) U18.U11(DQ11_B)
DDR_CH1_DQ4: U15.H4(DDR_CH1_DQ04) U18.V11(DQ10_B)
DDR_CH1_DQ5: U15.G1(DDR_CH1_DQ05) U18.AA11(DQ8_B)
DDR_CH1_DQ6: U15.G3(DDR_CH1_DQ06) U18.Y11(DQ9_B)
DDR_CH1_DQ7: U15.N11(DDR_CH1_DQ07) U18.Y9(DQ14_B)
DDR_CH1_DQ8: U15.L5(DDR_CH1_DQ08) U18.Y4(DQ6_B)
DDR_CH1_DQ9: U15.K4(DDR_CH1_DQ09) U18.AA4(DQ7_B)
DDR_CH1_DQ10: U15.N3(DDR_CH1_DQ10) U18.AA2(DQ0_B)
DDR_CH1_DQ11: U15.L3(DDR_CH1_DQ11) U18.Y2(DQ1_B)
DDR_CH1_DQ12: U15.P8(DDR_CH1_DQ12) U18.V4(DQ5_B)
DDR_CH1_DQ13: U15.N5(DDR_CH1_DQ13) U18.U2(DQ3_B)
DDR_CH1_DQ14: U15.P4(DDR_CH1_DQ14) U18.V2(DQ2_B)
DDR_CH1_DQ15: U15.P6(DDR_CH1_DQ15) U18.U4(DQ4_B)
DDR_CH1_DQ16: U15.AM4(DDR_CH1_DQ16) U18.B4(DQ7_A)
DDR_CH1_DQ17: U15.AL5(DDR_CH1_DQ17) U18.C4(DQ6_A)
DDR_CH1_DQ18: U15.AL3(DDR_CH1_DQ18) U18.B2(DQ0_A)
DDR_CH1_DQ19: U15.AJ3(DDR_CH1_DQ19) U18.C2(DQ1_A)
DDR_CH1_DQ20: U15.AJ5(DDR_CH1_DQ20) U18.F2(DQ3_A)
DDR_CH1_DQ21: U15.AH8(DDR_CH1_DQ21) U18.E4(DQ5_A)
DDR_CH1_DQ22: U15.AH6(DDR_CH1_DQ22) U18.F4(DQ4_A)
DDR_CH1_DQ23: U15.AH4(DDR_CH1_DQ23) U18.E2(DQ2_A)
DDR_CH1_DQ24: U15.AJ9(DDR_CH1_DQ24) U18.E9(DQ13_A)
DDR_CH1_DQ25: U15.AH10(DDR_CH1_DQ25) U18.F9(DQ12_A)
DDR_CH1_DQ26: U15.AM6(DDR_CH1_DQ26) U18.F11(DQ11_A)
DDR_CH1_DQ27: U15.AL7(DDR_CH1_DQ27) U18.B9(DQ15_A)
DDR_CH1_DQ28: U15.AR1(DDR_CH1_DQ28) U18.B11(DQ8_A)
DDR_CH1_DQ29: U15.AP4(DDR_CH1_DQ29) U18.E11(DQ10_A)
DDR_CH1_DQ30: U15.AJ11(DDR_CH1_DQ30) U18.C9(DQ14_A)
DDR_CH1_DQ31: U15.AR3(DDR_CH1_DQ31) U18.C11(DQ9_A)
DDR_CH1_DQS0_N: U15.L1(DDR_CH1_DQS0_N) U18.V10(DQS1_c_B)
DDR_CH1_DQS0_P: U15.K2(DDR_CH1_DQS0_P) U18.W10(DQS1_t_B)
DDR_CH1_DQS1_N: U15.P2(DDR_CH1_DQS1_N) U18.V3(DQS0_c_B)
DDR_CH1_DQS1_P: U15.N1(DDR_CH1_DQS1_P) U18.W3(DQS0_t_B)
DDR_CH1_DQS2_N: U15.AH2(DDR_CH1_DQS2_N) U18.E3(DQS0_c_A)
DDR_CH1_DQS2_P: U15.AJ1(DDR_CH1_DQS2_P) U18.D3(DQS0_t_A)
DDR_CH1_DQS3_N: U15.AL1(DDR_CH1_DQS3_N) U18.E10(DQS1_c_A)
DDR_CH1_DQS3_P: U15.AM2(DDR_CH1_DQS3_P) U18.D10(DQS1_t_A)
DDR_CH1_DTO0: U15.U9(DDR_CH1_DTO0)
DDR_CH1_DTO1: U15.T10(DDR_CH1_DTO1)
DDR_CH1_ODT_A: R88.1 U18.T2(ODT_CA_B)
DDR_CH1_ODT_B: R75.1 U18.G2(ODT_CA_A)
DDR_CH1_RST_B: R1482.1 U15.AB6(DDR_CH1_DCF18) U18.T11(RESET_N)
DDR_CH1_VREF: U15.U11(DDR_CH1_VREF)
DDR_CH1_ZQ: R261.2 U15.AF10(DDR_CH1_ZQ)
DDR_MEM0_ZQ0: R281.1 U17.A5(ZQ0)
DDR_MEM0_ZQ1: R276.1 U17.A8(ZQ1)
DDR_MEM1_ZQ0: R248.1 U18.A5(ZQ0)
DDR_MEM1_ZQ1: R252.1 U18.A8(ZQ1)
ENET0_INT_B: U15.AW53(GPT0_COMPARE) ; also on sheet 24
FTDI_M40_UART0_RX: U15.AM44(M40_I2C0_SCL) ; also on sheet 21
FTDI_M40_UART0_TX: U15.AU51(M40_I2C0_SDA) ; also on sheet 21
FTDI_UART0_RX: U15.AV50(UART0_RX) ; also on sheet 21
FTDI_UART0_TX: U15.AV48(UART0_TX) ; also on sheet 21
I2C1_1V8_SCL: R60.2 U15.AY52(GPT0_CLK) ; also on sheet 26 27
I2C1_1V8_SDA: R62.2 U15.AV52(GPT0_CAPTURE) ; also on sheet 26 27
IMX8_ON_OFF_BUTTON: U15.BE47(ON_OFF_BUTTON) ; also on sheet 20
JTAG_TCK: U15.BC51(JTAG_TCK) ; also on sheet 20
JTAG_TDI: U15.BE51(JTAG_TDI) ; also on sheet 20
JTAG_TDO: U15.BD52(JTAG_TDO) ; also on sheet 20
JTAG_TMS: U15.BA49(JTAG_TMS) ; also on sheet 20
JTAG_TRST#: R240.2 TP19.1(Pin1) U15.BE53(JTAG_TRST_B)
LT_BB_USB_OTG1_FLT_B: R1468.2 U64.9(1Y0) U216.4(Y)
MCLK_OUT0: U15.BD4(MCLK_OUT0) ; also on sheet 31
ON_REQ: R234.2 U15.BL51(PMIC_ON_REQ)
PMIC1_INT_B: U15.BH50(PMIC_INT_B) ; also on sheet 11
PMIC_EWARN: U15.BF50(PMIC_EARLY_WARNING) ; also on sheet 6 11
PMIC_I2C_SCL: U15.AY46(PMIC_I2C_SCL) ; also on sheet 6 11
PMIC_I2C_SDA: U15.BG51(PMIC_I2C_SDA) ; also on sheet 6 11
PMIC_POR_B_1V8: R239.2 U15.BE49(POR_B) ; also on sheet 6 11 20
RTC_XTALI: U15.BN47(RTC_XTALI) X1.2
RTC_XTALO: U15.BL47(RTC_XTALO) X1.1
SAI1_RXD: U15.AV4(SAI1_RXD) ; also on sheet 27
SAI1_TXC: U15.AU5(SAI1_TXC) ; also on sheet 27
SAI1_TXD: U15.AU1(SAI1_TXD) ; also on sheet 27
SAI1_TXFS: U15.AV2(SAI1_TXFS) ; also on sheet 27
SCU_BOOT_MODE0: U15.BB44(SCU_BOOT_MODE0) ; also on sheet 19
SCU_BOOT_MODE1: U15.BC45(SCU_BOOT_MODE1) ; also on sheet 19
SCU_BOOT_MODE2: U15.BJ53(SCU_BOOT_MODE2) ; also on sheet 19
SCU_BOOT_MODE3: U15.BA43(SCU_BOOT_MODE3) ; also on sheet 19
SCU_BOOT_MODE4: U15.AY42(SCU_BOOT_MODE4) ; also on sheet 19
SCU_BOOT_MODE5: U15.BK52(SCU_BOOT_MODE5) ; also on sheet 19
SCU_DBG_SEL: R1452.1 SW4.1(COMMON) U64.1(1S) U64.5(2S)
SCU_DEBUG_LED(SCU_GPIO0_02): U15.AW45(SCU_GPIO0_02) ; also on sheet 20
SCU_GPIO0_00: U15.AU43(SCU_GPIO0_00) U64.10(1Z)
SCU_GPIO0_01: U15.AV44(SCU_GPIO0_01) U64.6(2Z)
SCU_PMIC_ON_REQ: R233.2 R234.1 ; also on sheet 6 11
SCU_PMIC_STANDBY: U15.BA47(SCU_PMIC_STANDBY) ; also on sheet 6 11 20
SCU_UART0_RX: U64.2(1Y1) ; also on sheet 21
SCU_UART0_TX: U64.4(2Y1) ; also on sheet 21
SCU_WDOG_OUT: U15.BB50(SCU_WDOG_OUT) ; also on sheet 20
SUSCLK_32KHZ(SCU_GPIO0_07): TP15.1(Pin1) U15.BF48(SCU_GPIO0_07) ; also on sheet 31
WIFI_WAKE_B(ADC_IN2): U15.AP8(ADC_IN2) ; also on sheet 26
XTALI: U15.BN49(XTALI) X2.2
XTALO: U15.BL49(XTALO) X2.1
N21492894: R1453.1 SW4.2(NO)

Not connected (* = marked no-connect by the designer): U15 AB10(DDR_CH1_DCF24)* AB44(DDR_CH0_DCF24)* AC3(DDR_CH1_DCF22)* AC9(DDR_CH1_DCF23)* AC11(DDR_CH1_DCF20)* AC43(DDR_CH0_DCF20)* AC45(DDR_CH0_DCF23)* AC51(DDR_CH0_DCF22)* AE9(DDR_CH1_DCF21)* AE45(DDR_CH0_DCF21)* AF2(DDR_CH1_DCF25)* AF52(DDR_CH0_DCF25)* T2(DDR_CH1_DCF09)* T8(DDR_CH1_DCF13)* T46(DDR_CH0_DCF13)* T52(DDR_CH0_DCF09)* W3(DDR_CH1_DCF07)* W9(DDR_CH1_DCF06)* W11(DDR_CH1_DCF04)* W43(DDR_CH0_DCF04)* W45(DDR_CH0_DCF06)* W51(DDR_CH0_DCF07)* Y6(DDR_CH1_DCF02)* Y10(DDR_CH1_DCF05)* Y44(DDR_CH0_DCF05)* Y48(DDR_CH0_DCF02)*; U17 A1(DNU)* A2(DNU)* A11(DNU)* A12(DNU)* AA1(DNU)* AA12(DNU)* AB1(DNU)* AB2(DNU)* AB11(DNU)* AB12(DNU)* B1(DNU)* B12(DNU)* G11(NC)* K5(NC)* K8(NC)* N5(NC)* N8(NC)*; U18 A1(DNU)* A2(DNU)* A11(DNU)* A12(DNU)* AA1(DNU)* AA12(DNU)* AB1(DNU)* AB2(DNU)* AB11(DNU)* AB12(DNU)* B1(DNU)* B12(DNU)* G11(NC)* K5(NC)* K8(NC)* N5(NC)* N8(NC)*

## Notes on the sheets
sheet 13
- IMX8QM GND SECTIONS
sheet 14
- IMX8 SECTIONS_1
- I/O VOLTAGE :1.8V
- JTAG CONNECTOR
- AUDIO CONN(IN BB)
- Helper pull-up resistor is contingency due
  to MX8 output's weak source current
- SCU_GPIO0_03 used for WM8960 GPIO1
- PMIC_EARLY_WARNING from PMIC is O.D. P-chan to V+;
  QM enables on-chip pull-down by default.
  For PMIC_INT_B, QM software must enable on-chip pull-up.
- B2B CONNECTOR
- B2B CONNECTOR
- ROM enables Tamper
  on-chip pull-ups
- XTAL, 32.768KHz, 12.5pF,
  +/-20ppm, 70K,0.5uW(max)
- AUDIO CARD(IN BB)
- XTAL, 24MHz, 18pF,
  +/-30ppm, 40E, 300uW(max)
- The Termination resistors (R1483 and R1484) are added for Factory use only
  and do not connect for customer use cases.
- B2B CONNECTOR
- M.2 CONNECTOR
- AUDIO CODEC WM8960
- M.2 CONNECTOR
- Note: VSS_SCU_XTAL is connected to VSS_MAIN inside the IC.
  Therefore, do not connect to VSS_MAIN on the PCB.
  Use VSS_SCU_XTAL to create an island for the 24MHz crystal
- AUDIO CODEC WM8960
- AUDIO IN CARD (IN BB)
- M.2 CONNECTOR
- ARDUINO & MIKROBUS(IN BB)
- M.2 CONNECTOR
sheet 15
- IMX8 SECTIONS_2
- I/O VOLTAGE :3.3V
- 3-Wire Single-Ended MLB not supported by the processor.
  Other functions are supported as determined by IOMUX selection.
  If unused, adopters must follow the Hardware Developer's
  Guide Unused input/output terminations section.
- MLB(B2B CONNECTOR)
- NXP is aware that the UART net names are inaccurate. There is no plan
  to change the net names.
  Adopters please note:
  UART3 net name on contact AR47/AU53 should be UART4.
  UART4 net name on contact AP44/AU47 should be UART3.
  2-Wire AUDIN function not available on Base Board.
- 6-Wire Differential MLB not supported by the processor.
  Adopters must follow the Hardware Developer’s Guide
  Unused input/output terminations section.
- I/O VOLTAGE :1.8V
- ARDUINO & MIKROBUS(IN BB)
- I/O VOLTAGE :1.8V
- FTDI DEBUG
- AUDIO CONNECTOR,(IN BB)
- I2C ALSO USED FOR CAN GPIO EXPANDER (IN BB)
- ENET CARD SPI(IN BB)
- M.2,WM8960
- Three interrupts are connected to
  M4_GPT1 configured as LSIO GPIO.
  These are pulled to 1.8 V on Sheet 30 to avoid false
  triggering when the Base Board is not installed.
  The Base Board has voltage translation as needed.
- CAN signals ERR, WAKE, and INT are combined together on
  the Base Board to provide the CAN_INT_B signal.
- FTDI DEBUG
- DBG CONNECTOR(IN BB)
- M.2 CONNECTOR
- SIM(B2B CONNECTOR)
- M.2 CONNECTOR
- I/O VOLTAGE :3.3V
- CAN 0,1,2(B2B CONNECTOR)
sheet 16
- LPDDR4 DRAM 1 OF 2
- Total System DRAM = 6 Gbyte
- Do Not
  Connect
  DCF09
- Pullup ODT_CA_A/B on LPDDR4 memory.
  Do not connect this pin to the i.MX8QM
- Do Not
  Connect
  DCF25
- The processor requires x16 for each chip inside the DRAM package.
  The x8 configuration is not compatible.
sheet 17
- LPDDR4 DRAM 2 OF 2
- Total System DRAM = 6 Gbyte
- Do Not
  Connect
  DCF09
- Pullup ODT_CA_A/B on LPDDR4 memory.
  Do not connect this pin to the i.MX8QM
- Do Not
  Connect
  DCF25
- The processor requires x16 for each chip inside the DRAM package.
  The x8 configuration is not compatible.
